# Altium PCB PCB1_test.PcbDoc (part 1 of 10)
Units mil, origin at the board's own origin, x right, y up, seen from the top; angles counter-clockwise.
Board outline 6690 x 6690 mil, 6 copper layers (Layer 1 - Top Layer, Layer 2 - GND, Layer 3 - PWR, Layer 4 - Signal, Layer 5 - GND, Layer 6 - Bottom Layer), stack 80.244 mil thick; 821 components, 458 nets, 3752 pads, 1525 vias.
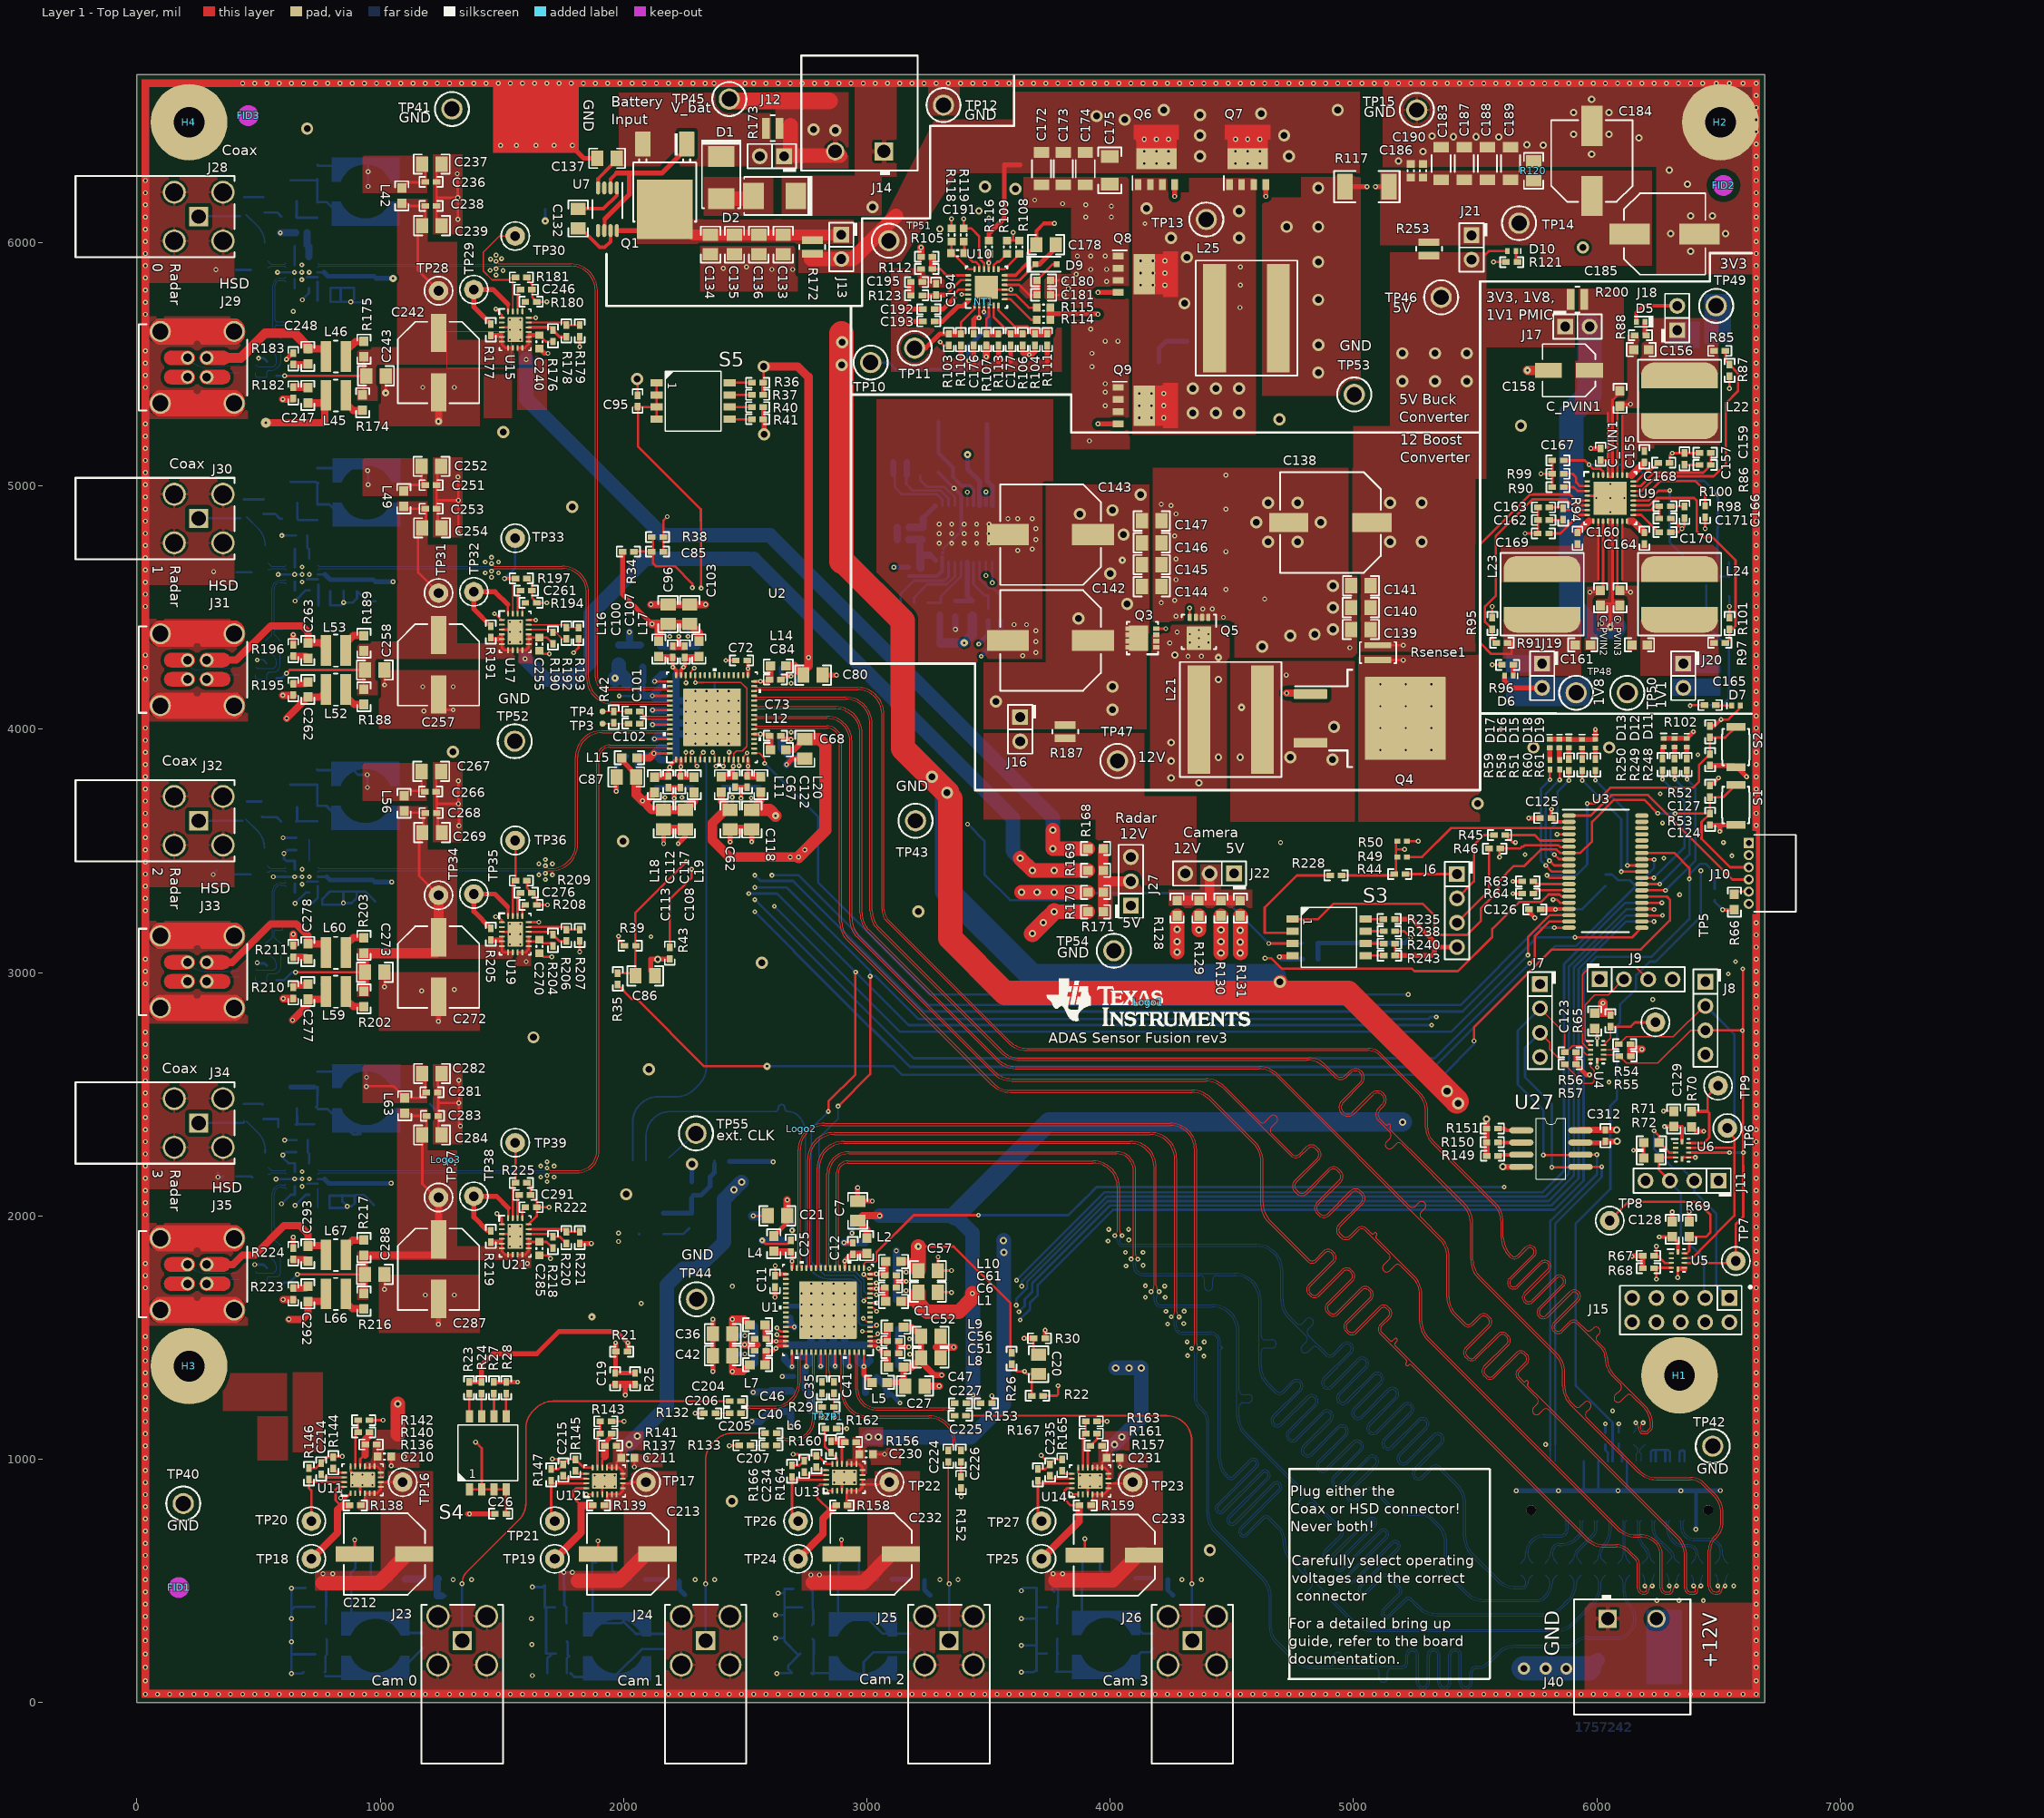
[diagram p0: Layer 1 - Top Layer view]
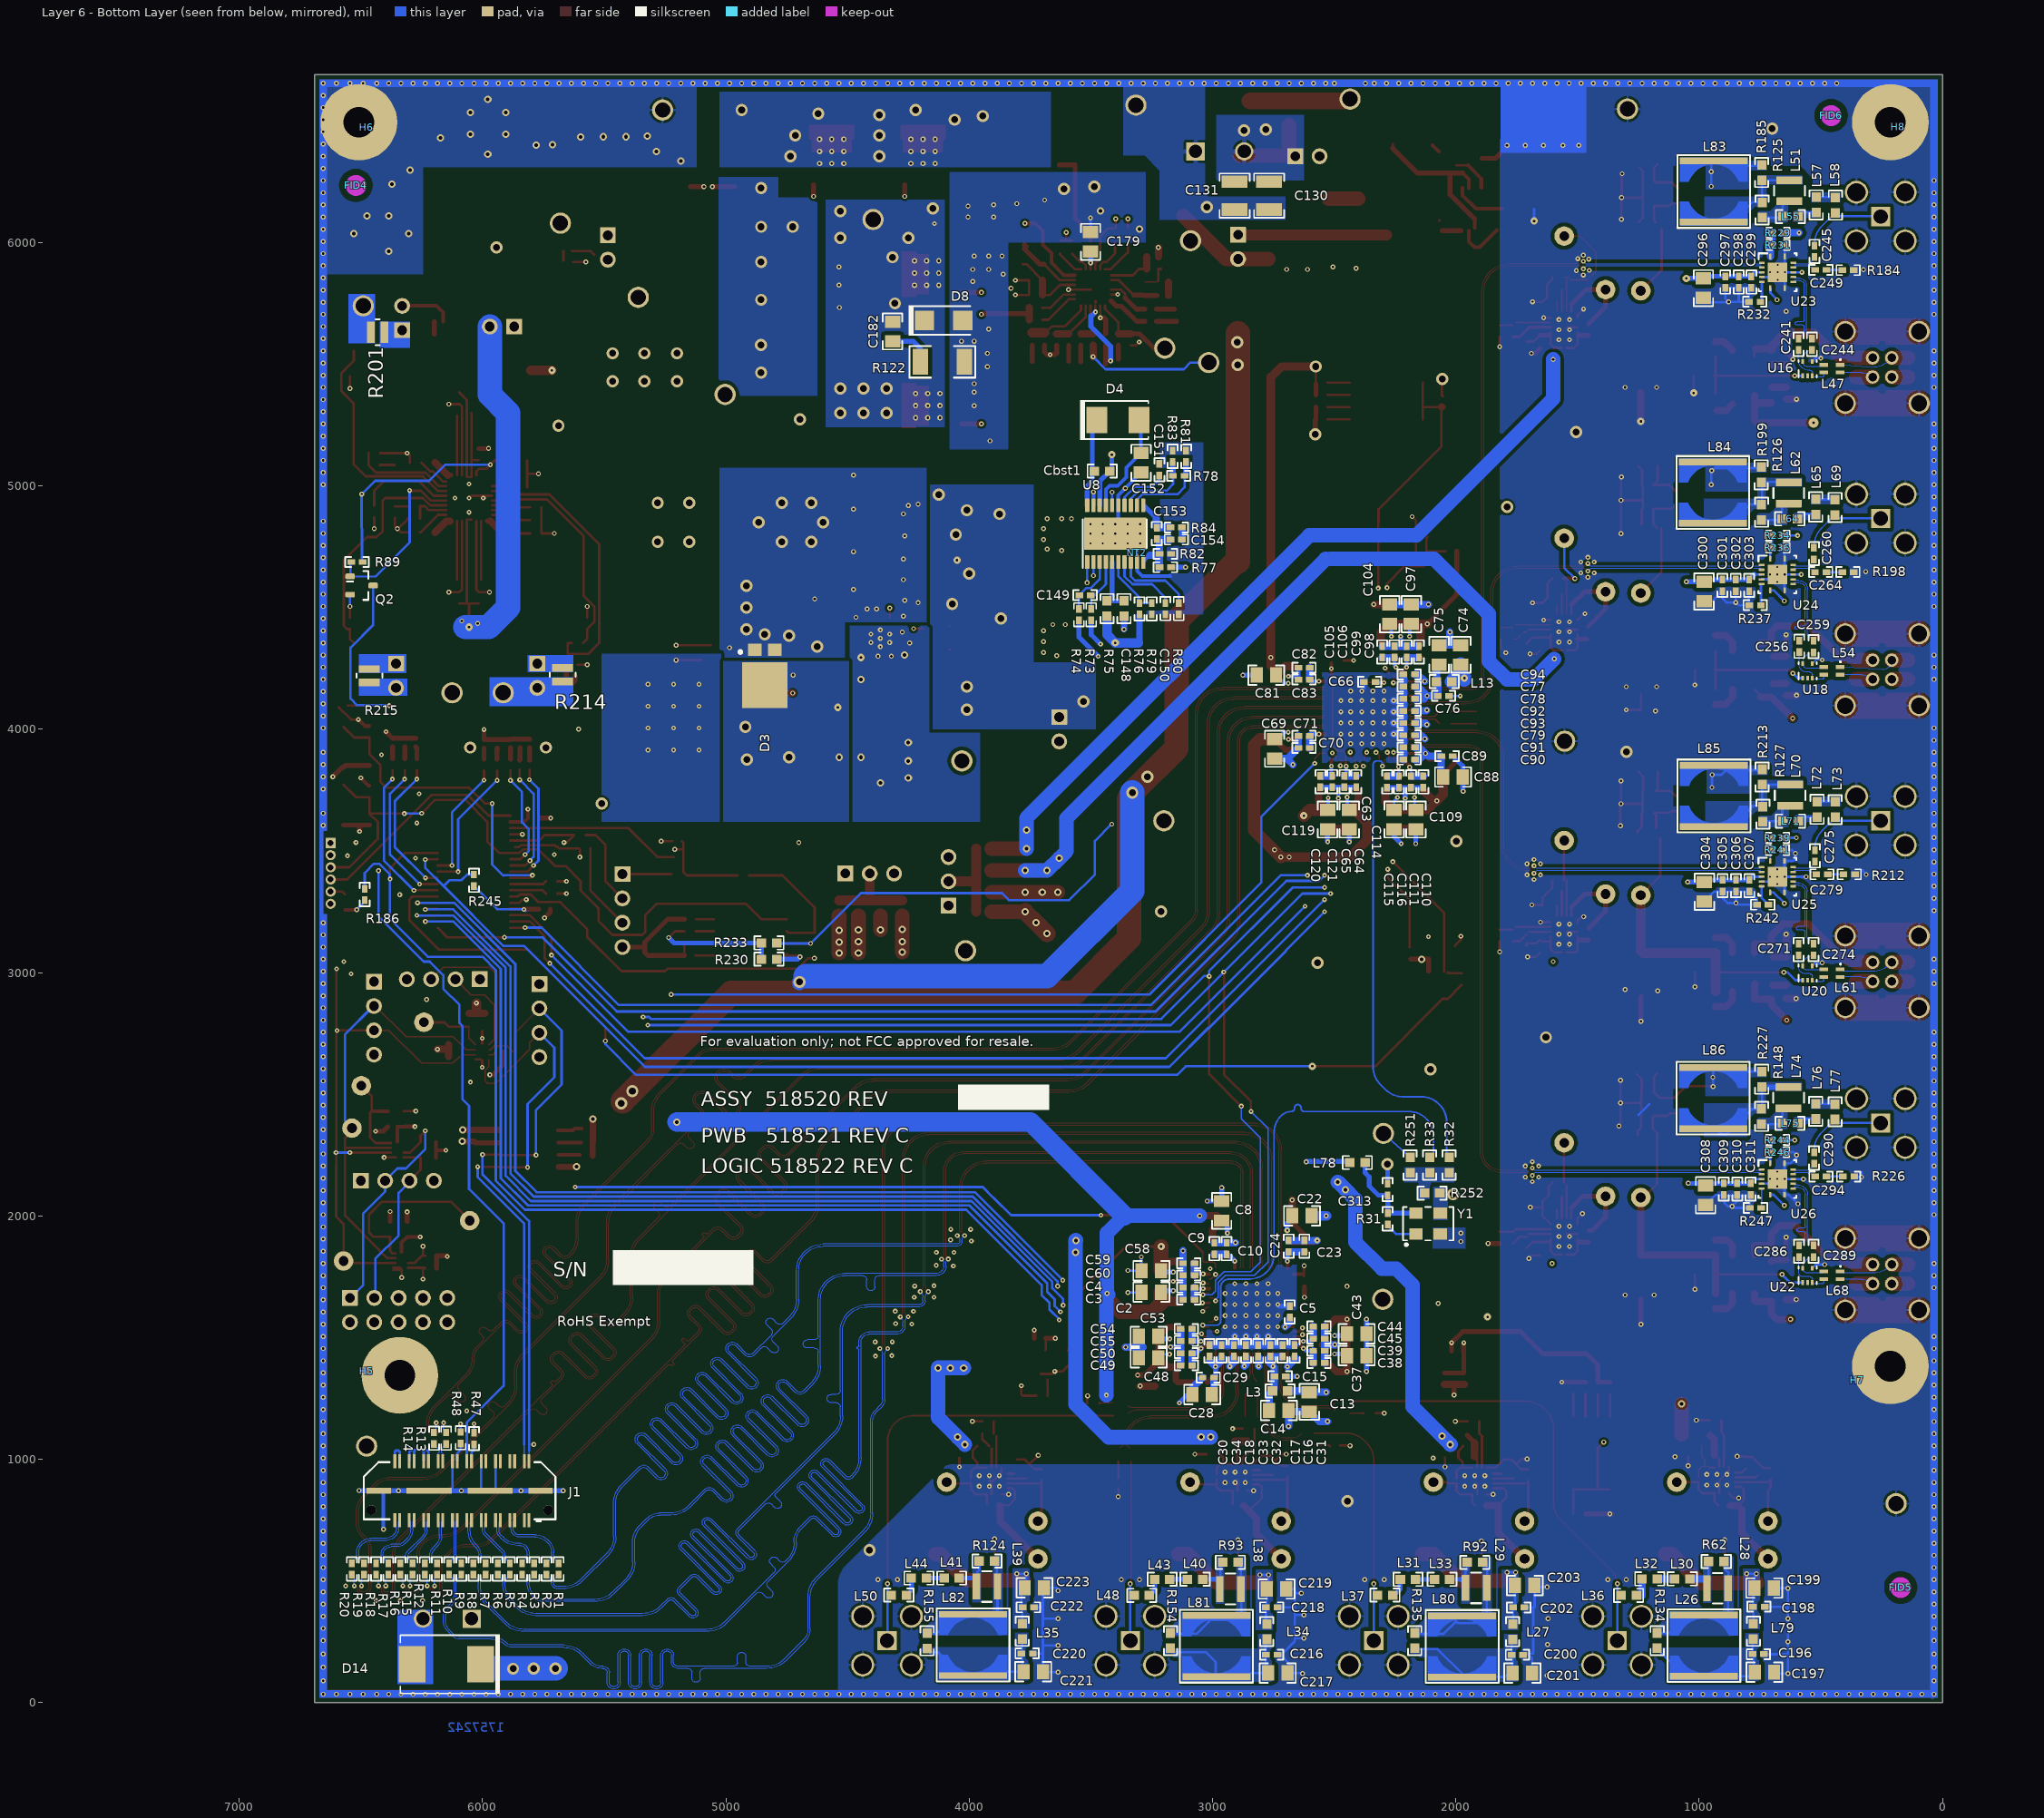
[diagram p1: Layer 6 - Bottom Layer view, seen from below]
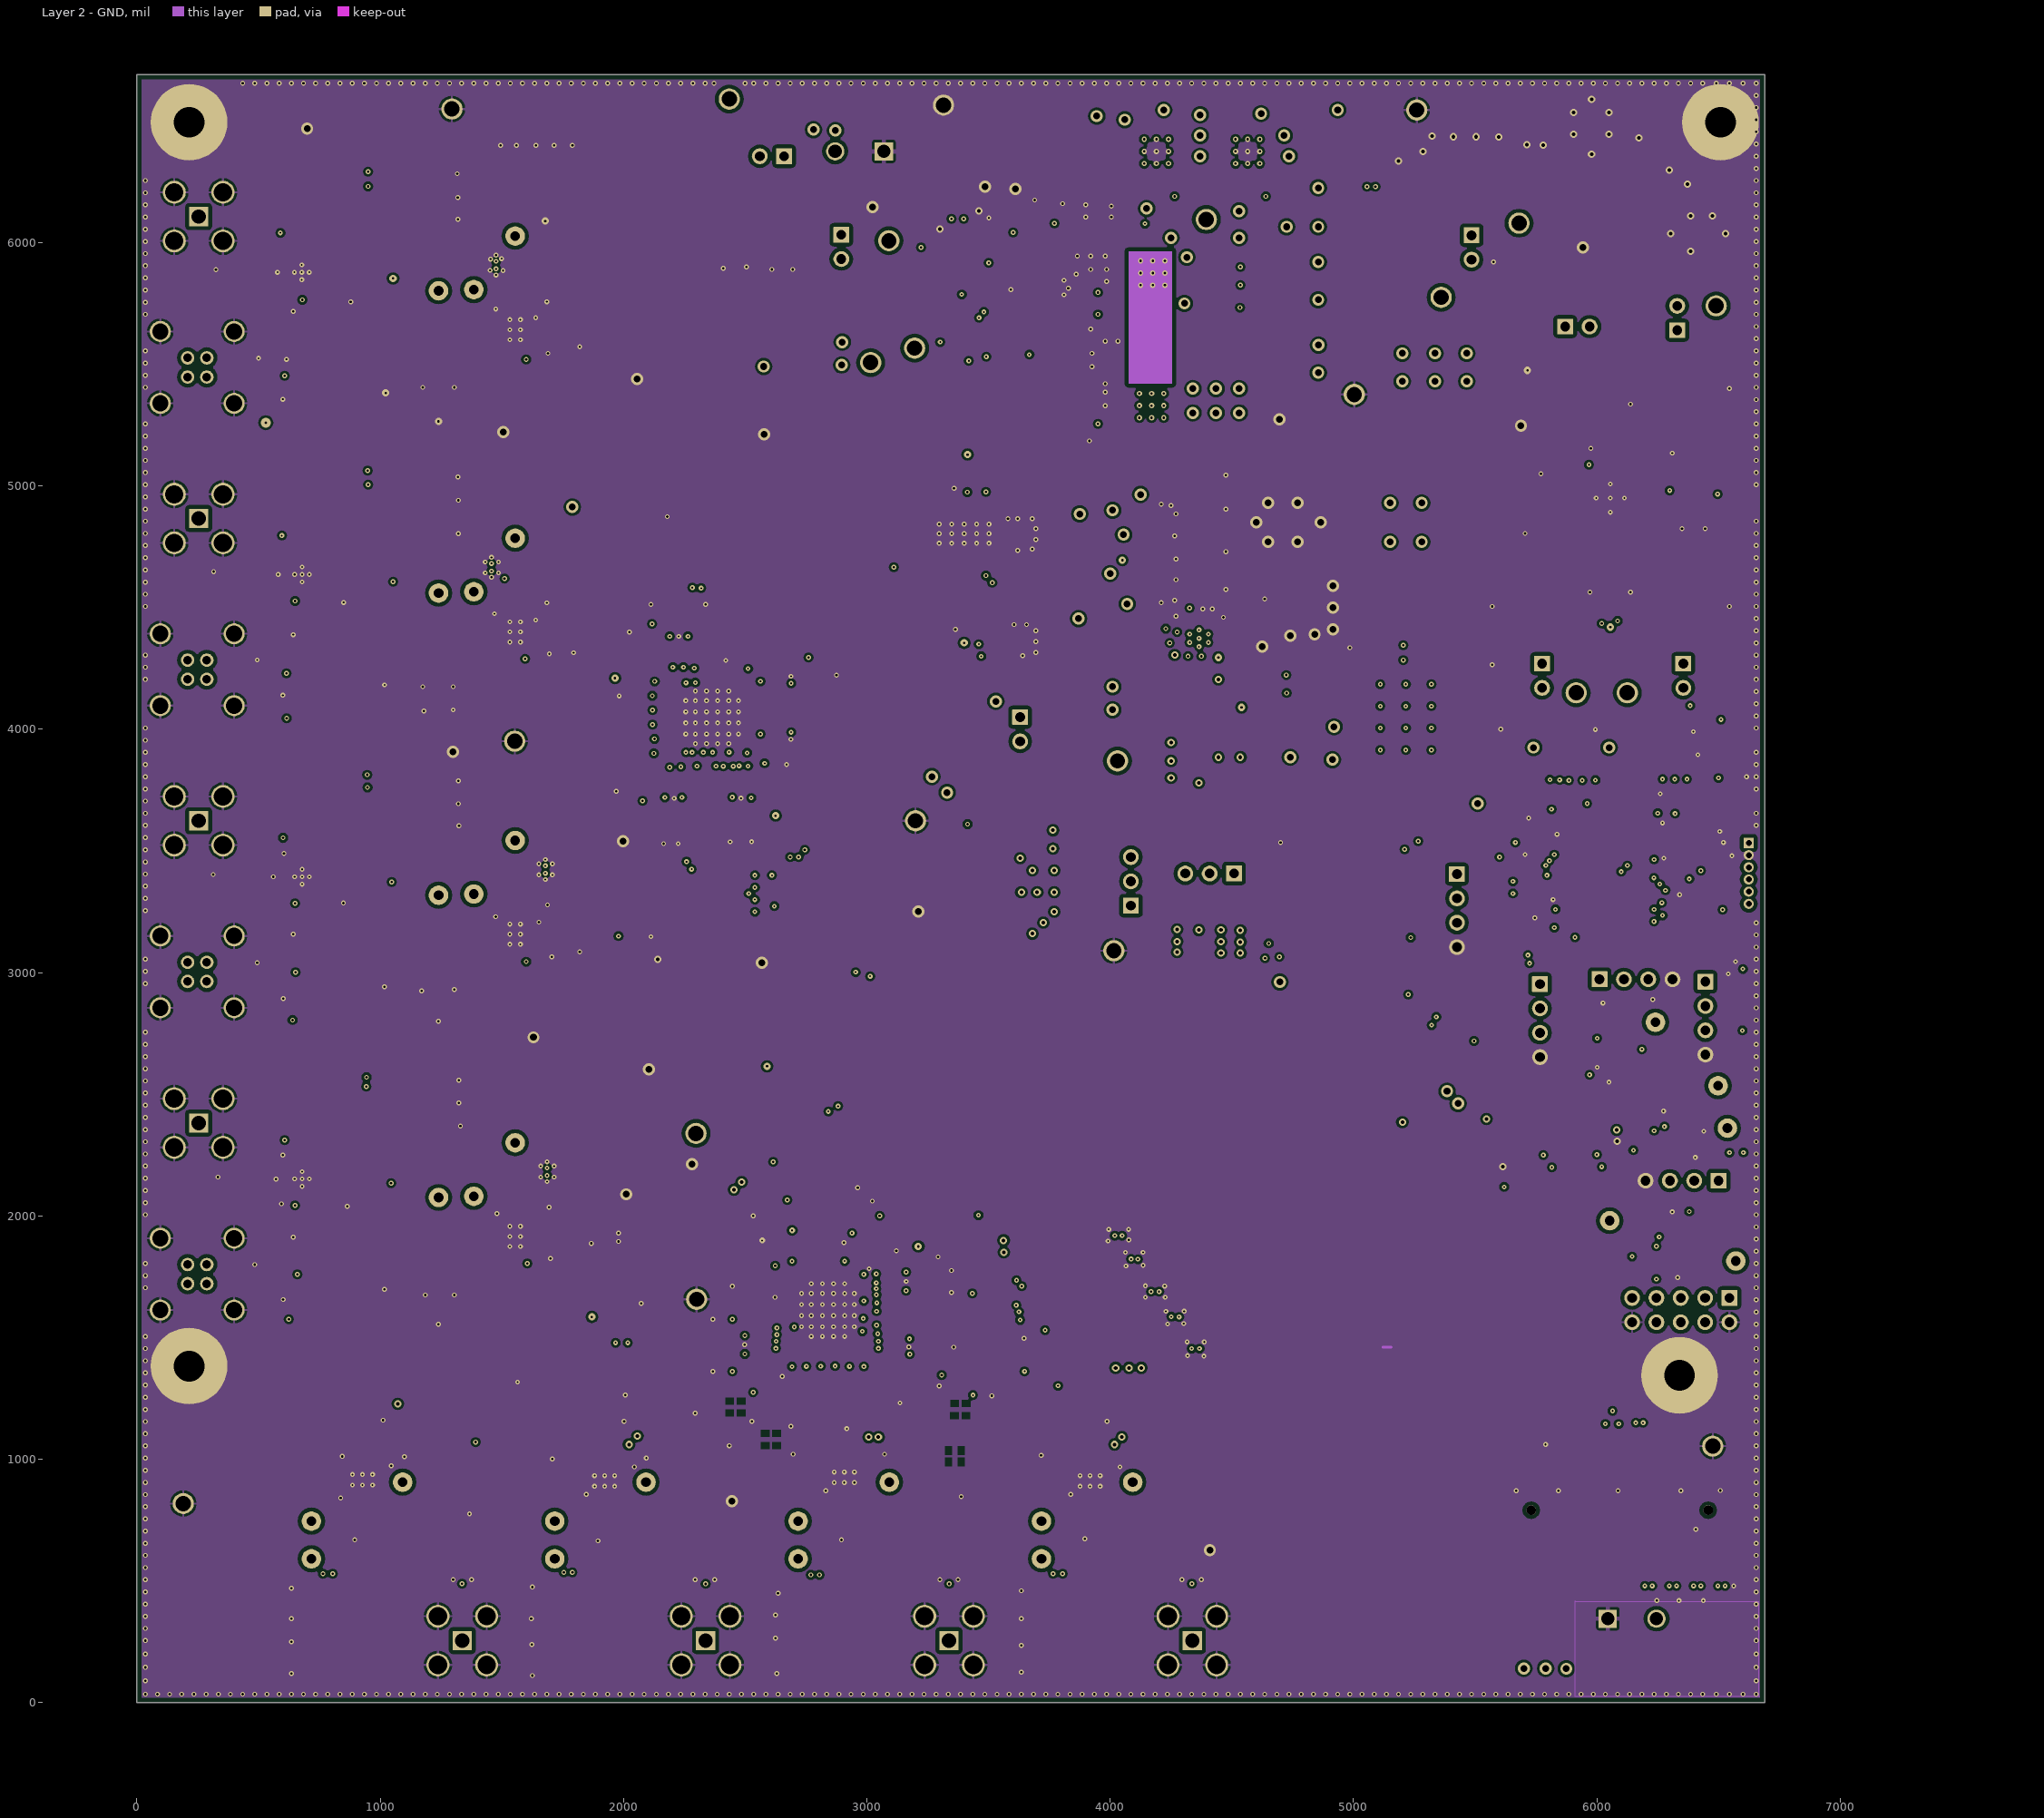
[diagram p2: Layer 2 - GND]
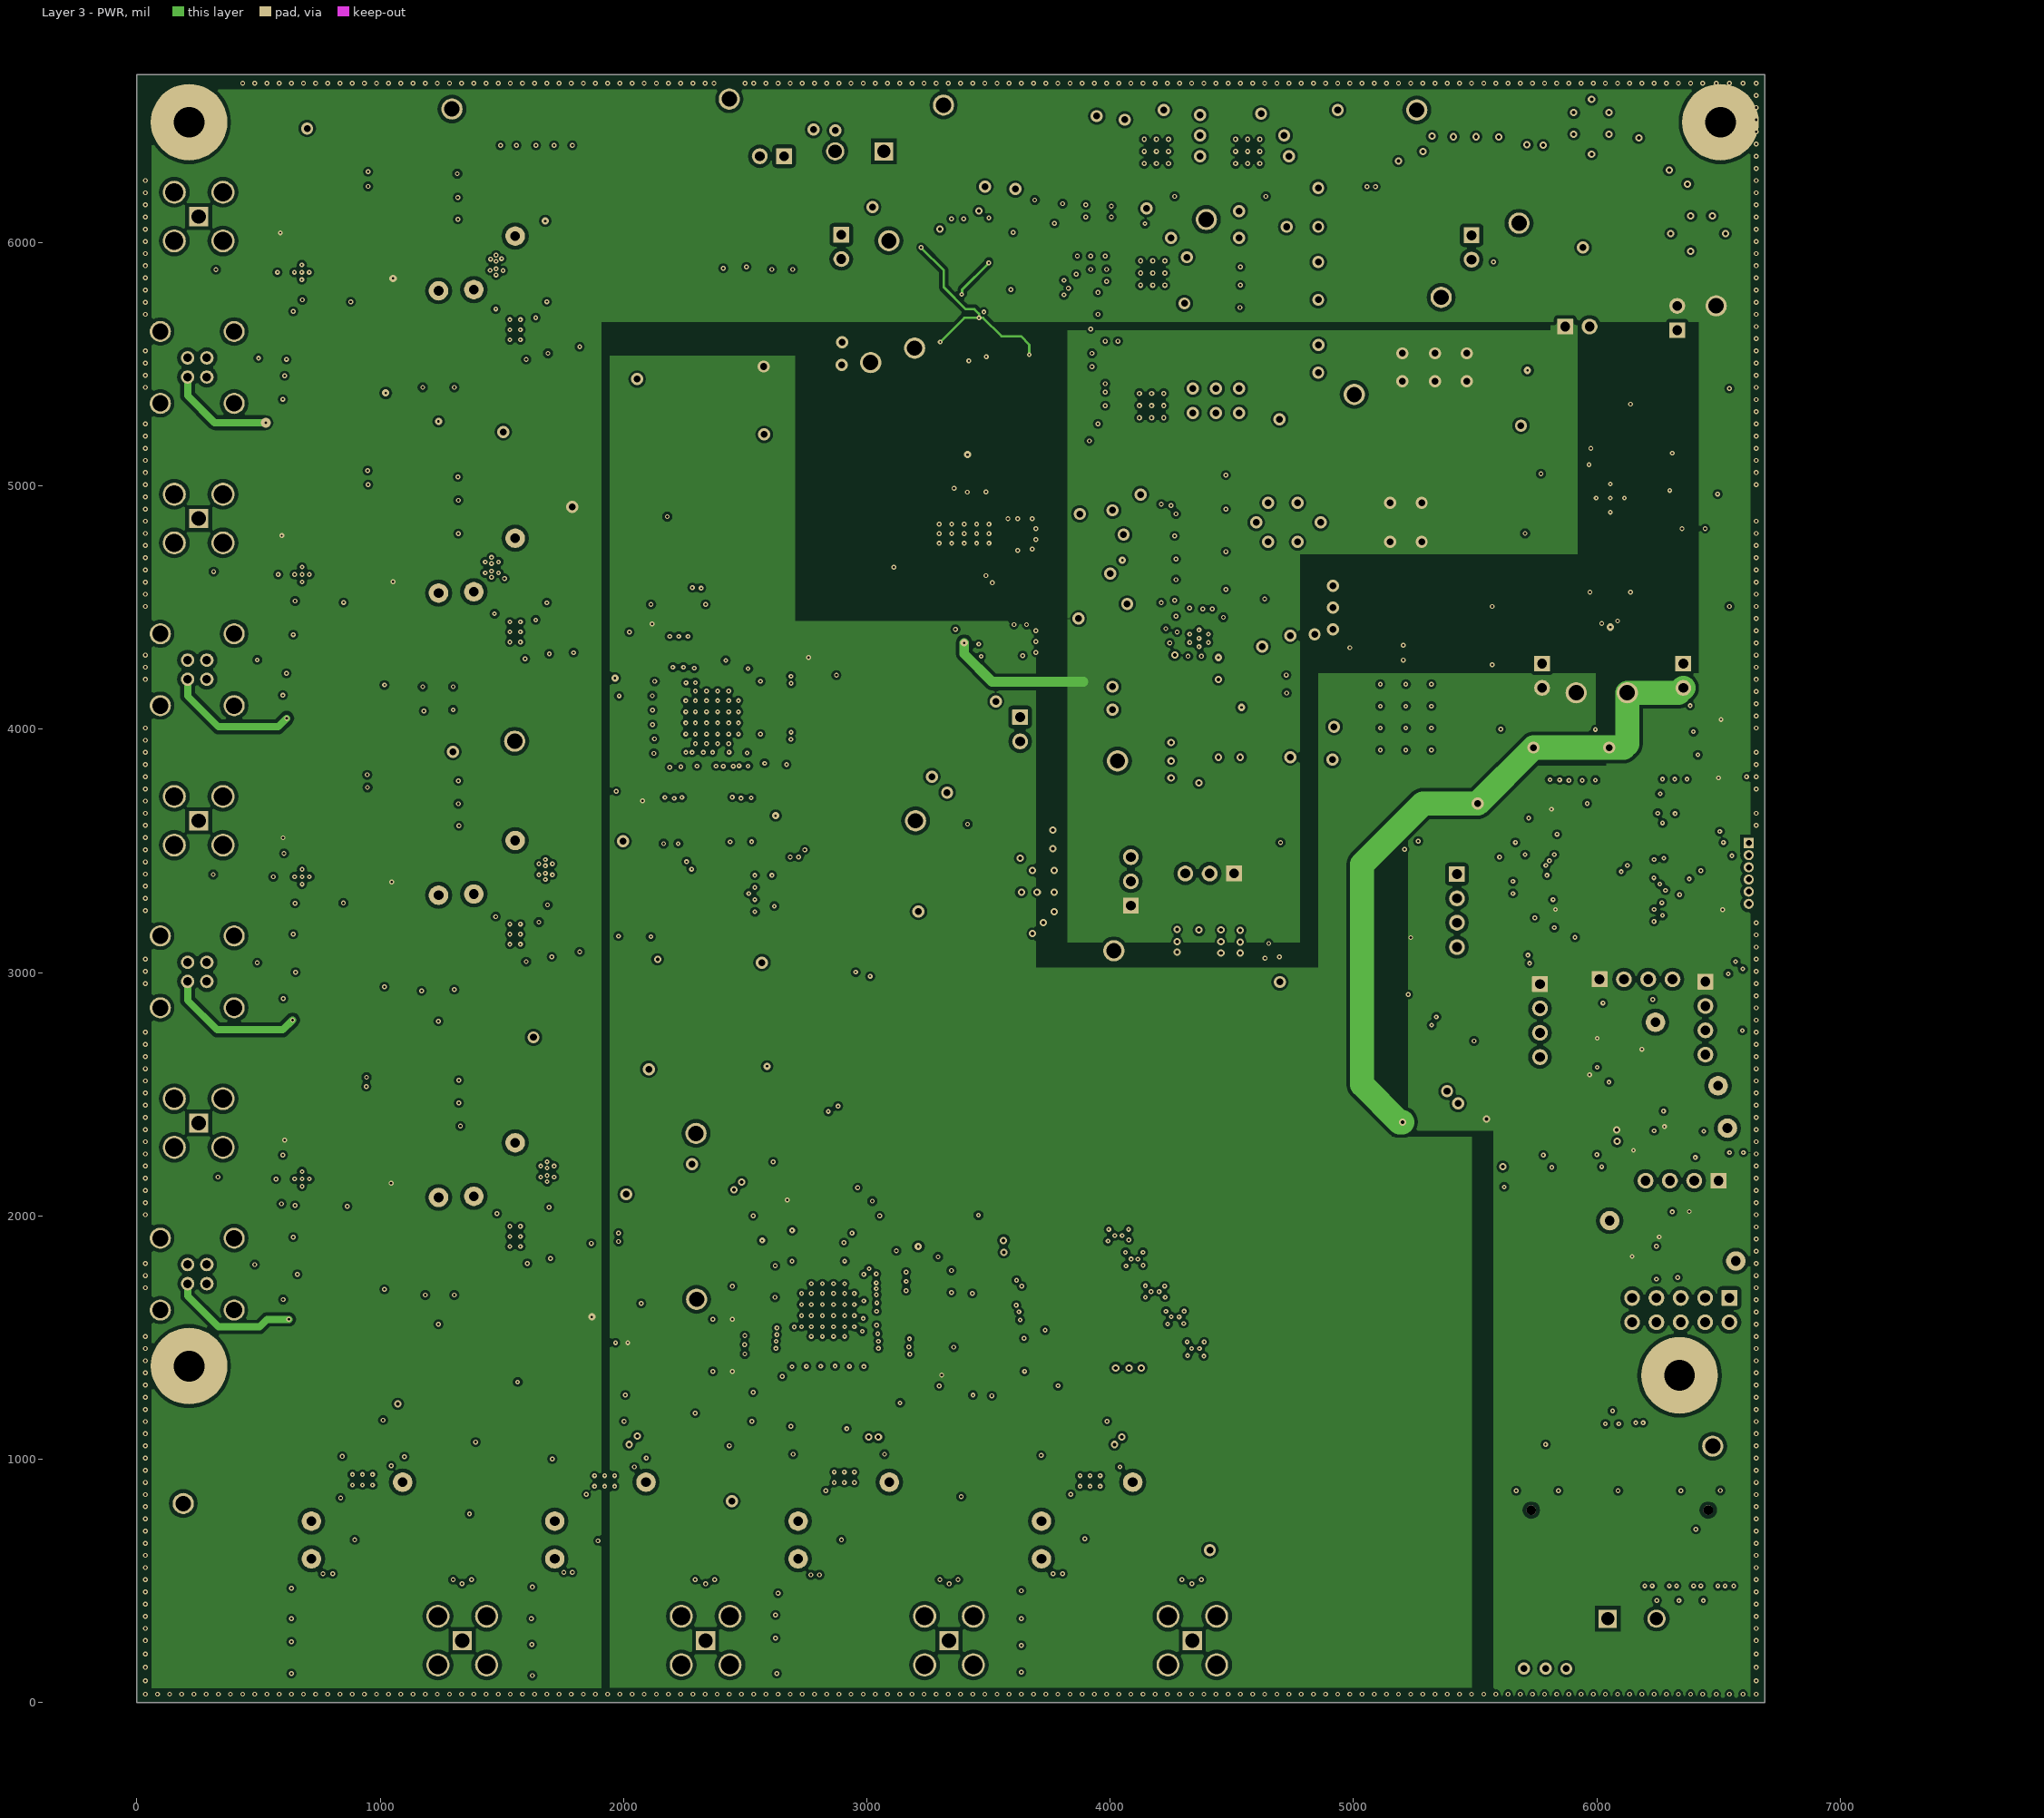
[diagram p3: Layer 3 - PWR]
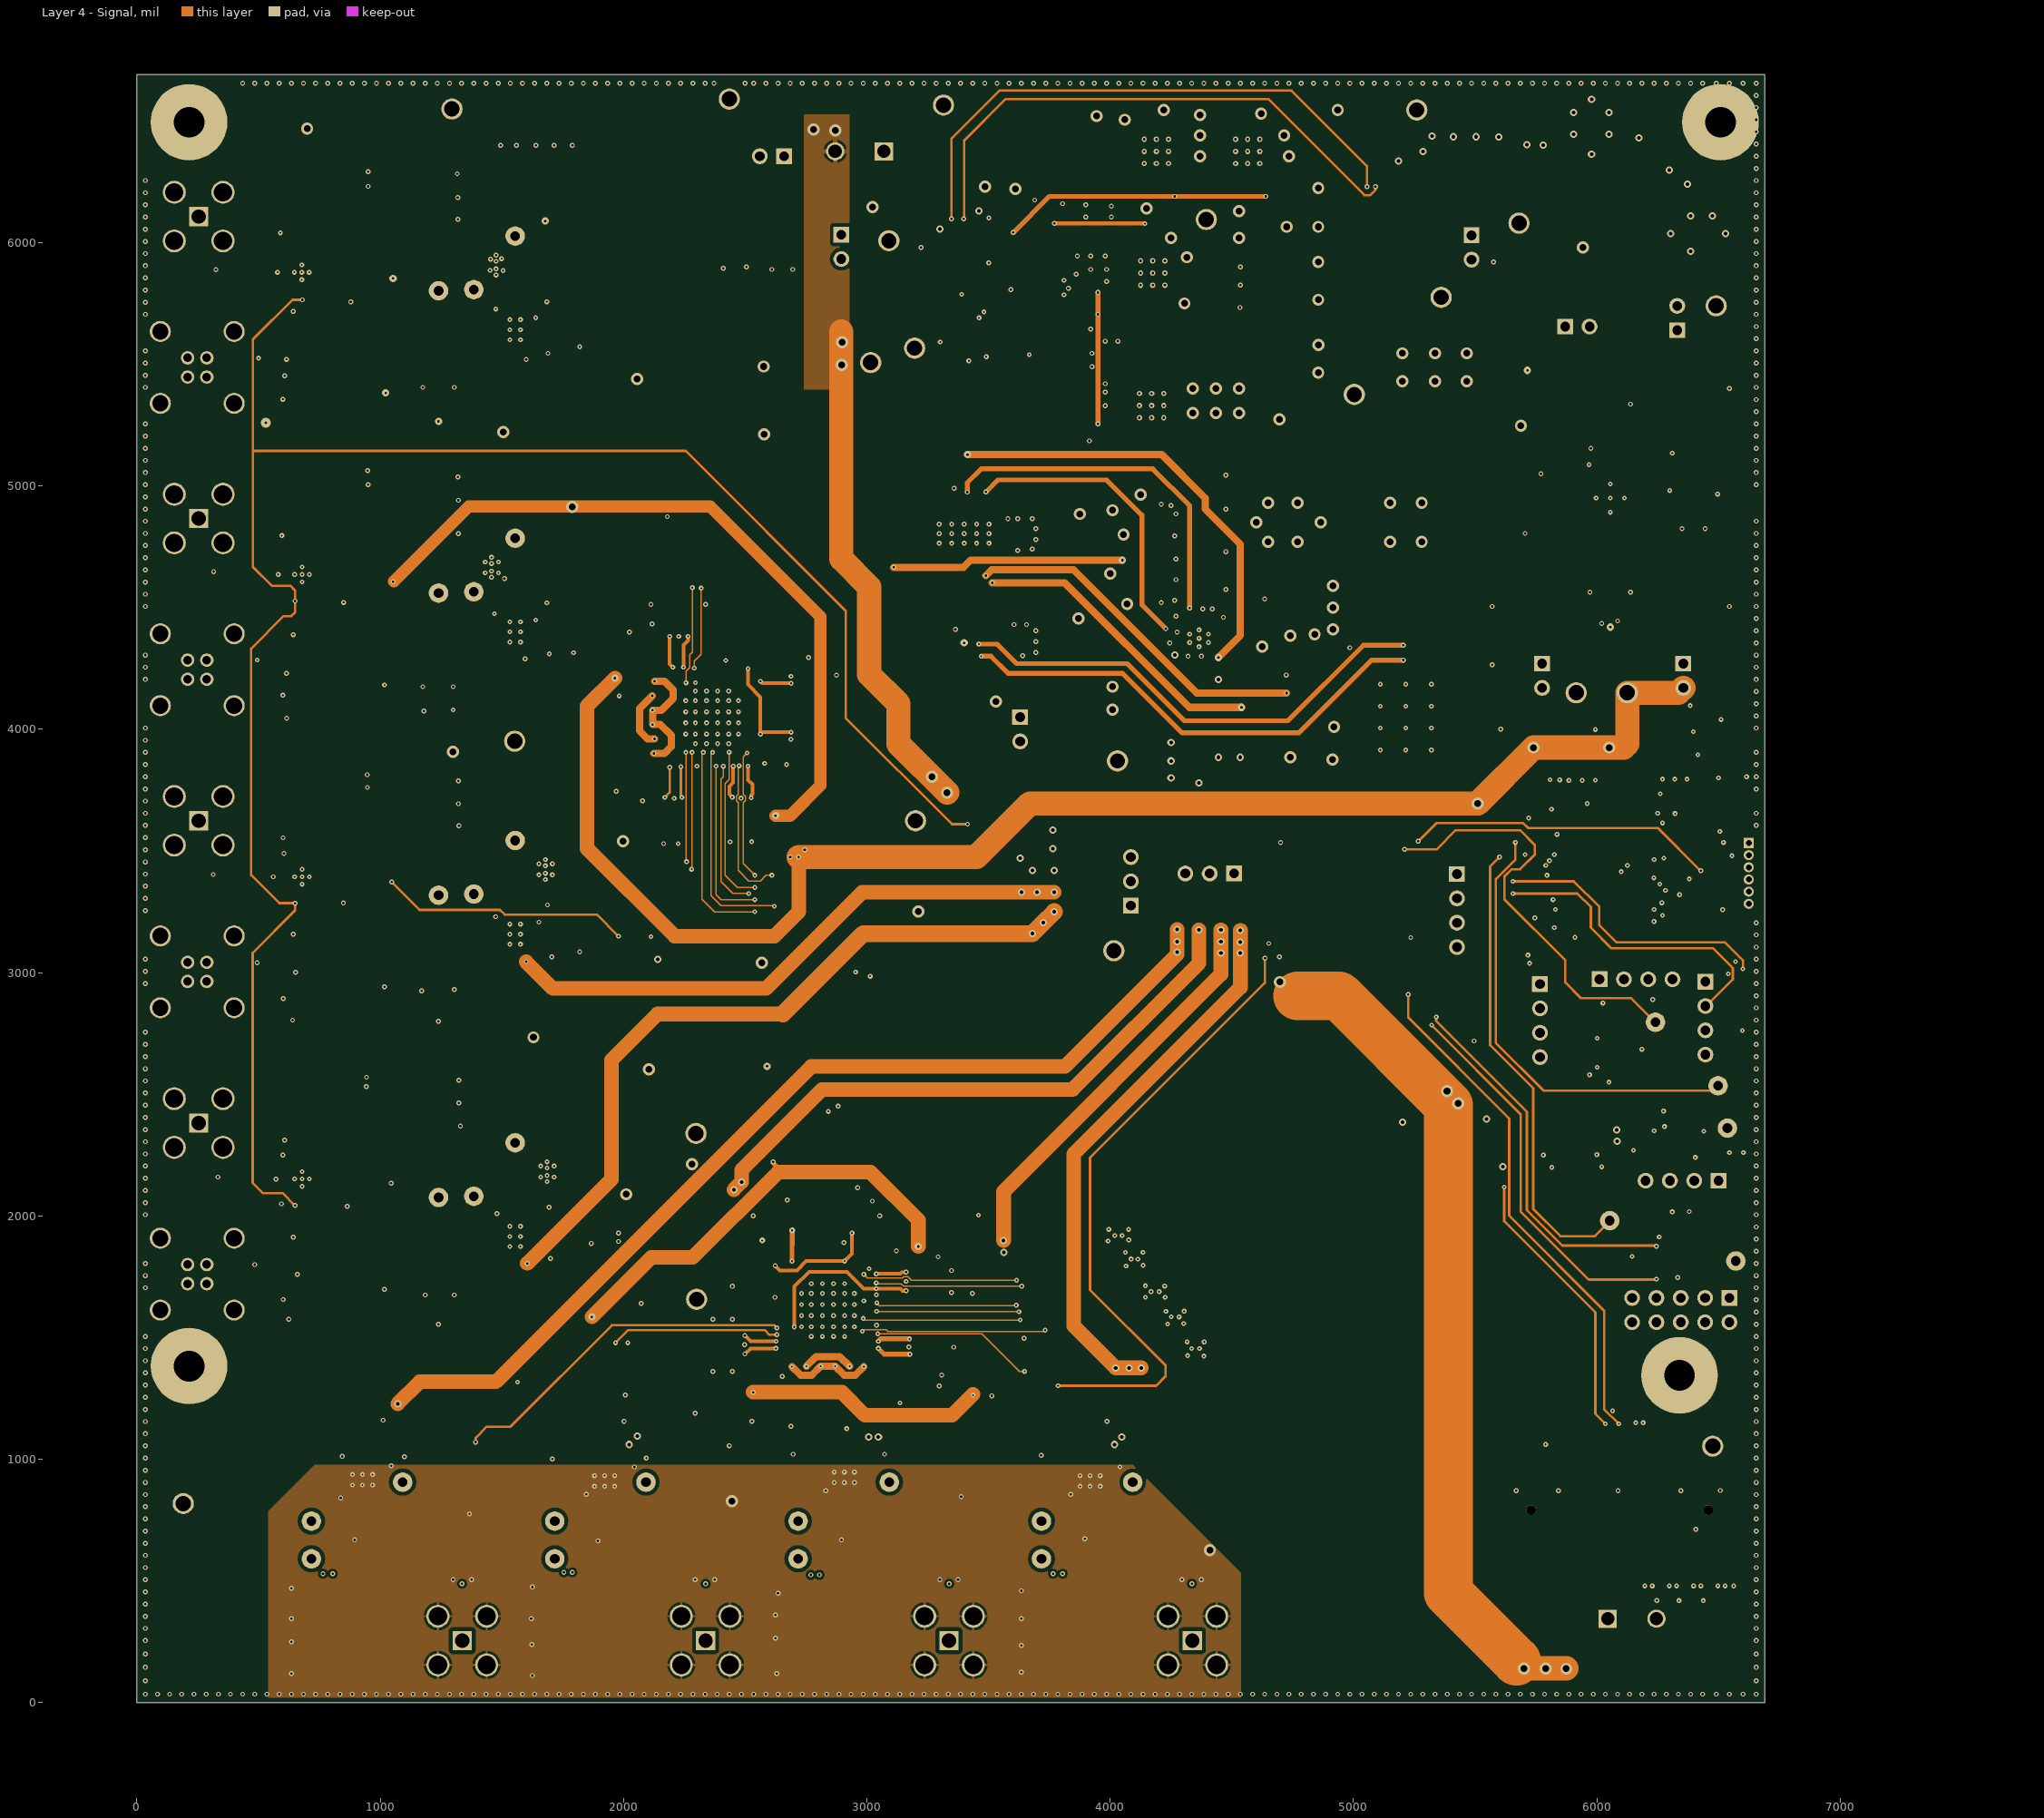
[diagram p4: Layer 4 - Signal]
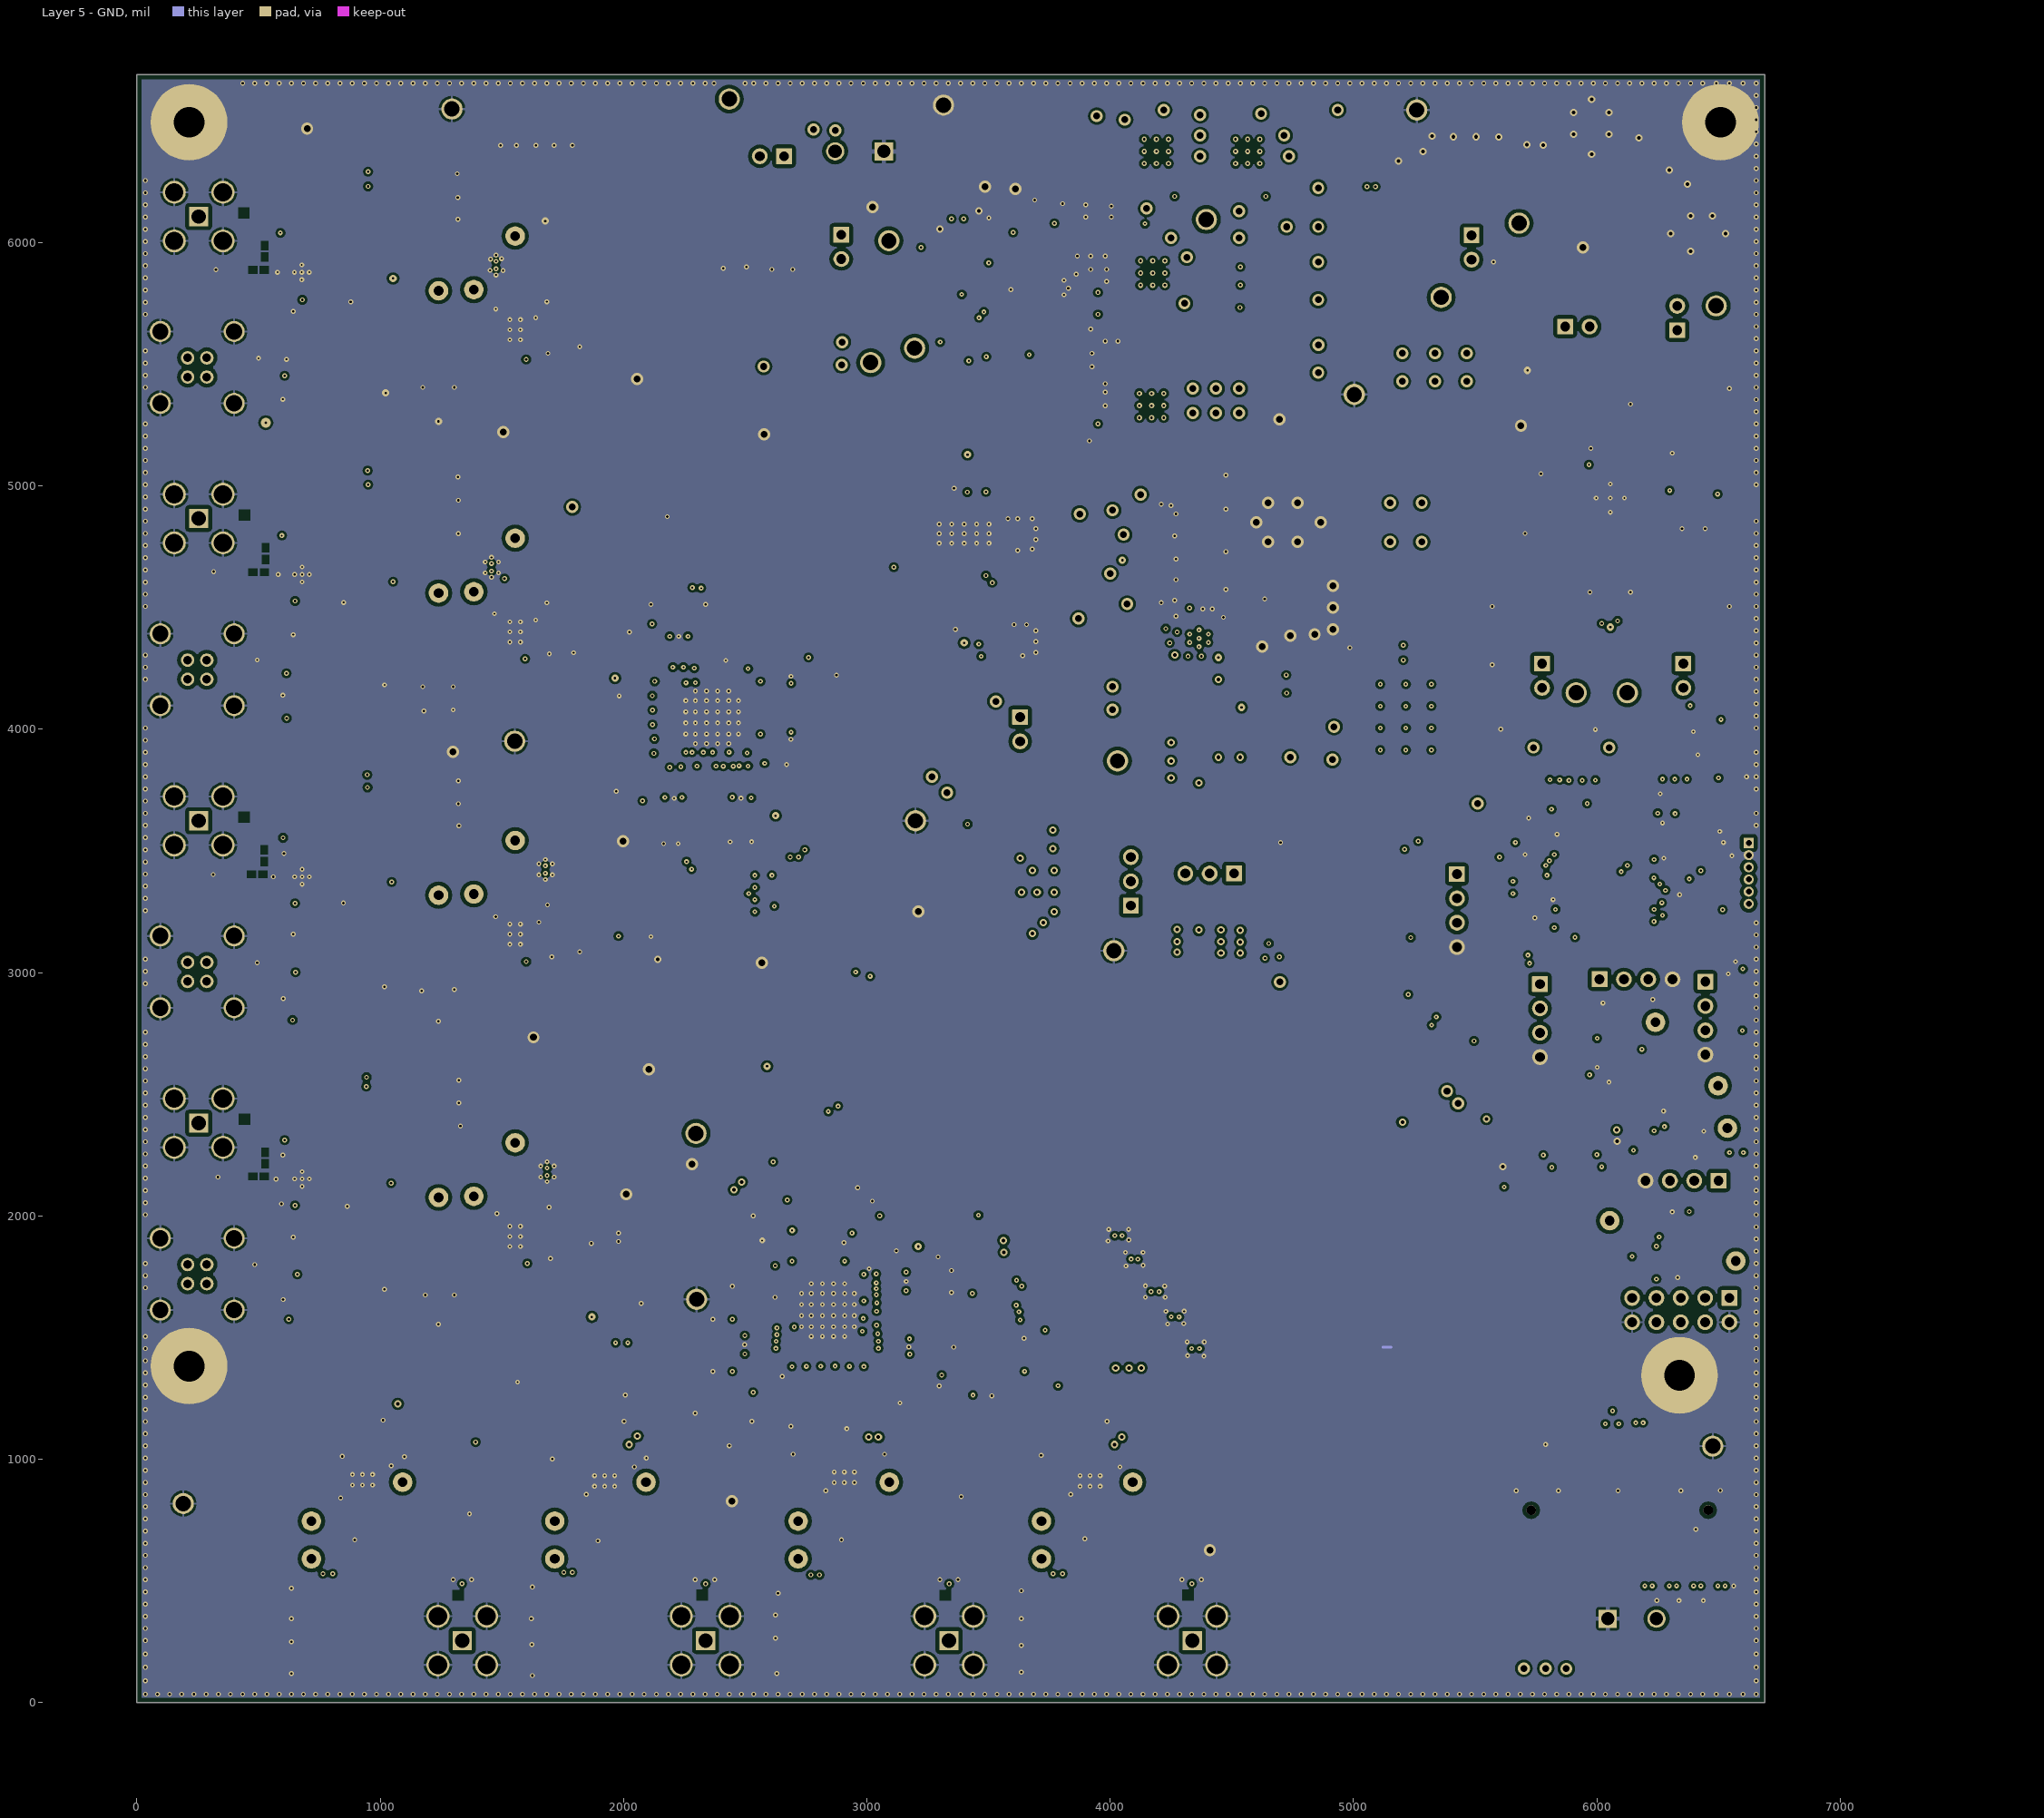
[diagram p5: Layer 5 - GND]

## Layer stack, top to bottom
Top Solder: solder mask 0.5, Solder Resist, Dk 3.5
Layer 1 - Top Layer: signal copper 1.7
Dielectric1: prepreg 4.055, 370HR, Dk 4.2
Layer 2 - GND: signal copper 1.181
Dielectric2: core 27.95, 370HR, Dk 4.2
Layer 3 - PWR: signal copper 1.181
Dielectric3: prepreg 8.11, 370HR, Dk 4.2
Layer 4 - Signal: signal copper 1.181
Dielectric4: core 27.95, 370HR, Dk 4.2
Layer 5 - GND: signal copper 1.181
Dielectric5: prepreg 4.055, 370HR, Dk 4.2
Layer 6 - Bottom Layer: signal copper 1.7
Bottom Solder: solder mask 0.5, Solder Resist, Dk 3.5

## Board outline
0,0 6690,0 6690,6690 0,6690

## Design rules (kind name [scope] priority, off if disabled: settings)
AcuteAngle [All] p1: minimum=4.49000000000000E+0001 checktracksonly=FALSE
AssemblyTestPointUsage [All] p1: valid=2
Clearance Clearance_Keepouts [((IsTrack Or IsArc) And Not InPoly) And IsFree and IsKeepOut vs ((IsTrack Or IsArc) And Not InPoly) And IsFree and IsKeepOut] p1: gap=0 ignorepadtopadclearanceinfootprint=FALSE
Clearance Clearance_BoardEdge_MountingHoles [OnCopper and InComponentClass('Mounting Holes') vs IsKeepOut] p2: gap=30 ignorepadtopadclearanceinfootprint=FALSE except(0: Arc-Hole Track-Hole SMDPad-Hole THPad-Hole Via-Hole Fill-Hole Poly-Hole Region-Hole Text-Hole)
Clearance Clearance_BoardEdge_Poly [OnCopper and InPoly vs IsKeepOut] p3: gap=25 ignorepadtopadclearanceinfootprint=FALSE except(0: Arc-Hole Track-Hole SMDPad-Hole THPad-Hole Via-Hole Fill-Hole Poly-Hole Region-Hole Text-Hole)
Clearance Clearance_BoardEdge [OnCopper and Not InComponentClass('Logo') and not InComponentClass('FiducialMark') and not InRegion(1000,500,4000,800) and Not IsKeepout vs IsKeepOut] p4: gap=75 ignorepadtopadclearanceinfootprint=FALSE except(0: Arc-Hole Track-Hole SMDPad-Hole THPad-Hole Via-Hole Fill-Hole Poly-Hole Region-Hole Text-Hole)
Clearance Clearance_Poly [InPolygon] p5: gap=15 ignorepadtopadclearanceinfootprint=FALSE except(0: Arc-Hole Track-Hole SMDPad-Hole THPad-Hole Via-Hole Fill-Hole Poly-Hole Region-Hole Text-Hole; 10: Via-Fill Via-Poly Via-Region)
Clearance [All] p6: gap=4 ignorepadtopadclearanceinfootprint=FALSE except(0: Arc-Hole Track-Hole SMDPad-Hole THPad-Hole Via-Hole Fill-Hole Poly-Hole Region-Hole Text-Hole)
ComponentClearance ComponentClearance_MountingHoles_FiducialMarks [InComponentClass('Mounting Holes') vs InComponentClass('FiducialMark')] p1: gap=50 collisioncheckmode=3 verticalgap=10 showdistances=FALSE
ComponentClearance ComponentClearance_Header [InComponent('J*')] p2: gap=0 collisioncheckmode=3 verticalgap=0 showdistances=FALSE
ComponentClearance ComponentClearance_Shunt [InComponentClass('Header') vs InComponentClass('Shunt')] p3: gap=0 collisioncheckmode=3 verticalgap=0 showdistances=FALSE
ComponentClearance ComponentClearance_Logo [InComponentClass('Logo')] p4: gap=50 collisioncheckmode=3 verticalgap=10 showdistances=FALSE
ComponentClearance ComponentClearance_ScrewToNut [(HasFootprint('NY PMS 440 0025 PH')) vs (HasFootprint('Keystone_1902C'))] p5: gap=5 collisioncheckmode=3 verticalgap=10 showdistances=FALSE
ComponentClearance ComponentClearance_MountingHoles [InComponentClass('Mounting Holes')] p6: gap=100 collisioncheckmode=3 verticalgap=0 showdistances=FALSE
ComponentClearance ComponentClearance_SmallPassives [HasFootprint('0201*') or HasFootprint('0402*') or HasFootprint('0508') or HasFootprint('0603*') or HasFootprint('0612') or HasFootprint('0805*') or HasFootprint('0815*') or HasFootprint('0830*') or HasFootprint('1206*') or HasFootprint('1210*') or HasFootprint('1808*') or HasFootprint('1812*') or HasFootprint('1825*') or HasFootprint('2010*') or HasFootprint('2220*') or HasFootprint('2225*') or HasFootprint('2512*') or HasFootprint('2728*') or HasFootprint('3518*') vs HasFootprint('0201*') or HasFootprint('0402*') or HasFootprint('0508') or HasFootprint('0603*') or HasFootprint('0612') or HasFootprint('0805*') or HasFootprint('0815*') or HasFootprint('0830*') or HasFootprint('1206*') or HasFootprint('1210*') or HasFootprint('1808*') or HasFootprint('1812*') or HasFootprint('1825*') or HasFootprint('2010*') or HasFootprint('2220*') or HasFootprint('2225*') or HasFootprint('2512*') or HasFootprint('2728*') or HasFootprint('3518*')] p7: gap=10 collisioncheckmode=3 verticalgap=10 showdistances=FALSE
ComponentClearance ComponentClearance_THtoSMT [IsThruComponent vs IsSMTComponent] p8: gap=20 collisioncheckmode=3 verticalgap=30 showdistances=FALSE
ComponentClearance ComponentClearance_THtoTH [IsThruComponent vs IsThruComponent] p9: gap=40 collisioncheckmode=3 verticalgap=30 showdistances=FALSE
ComponentClearance [All] p10: gap=10 collisioncheckmode=3 verticalgap=10 showdistances=FALSE
DiffPairsRouting "CSI2 Routing old" [InDifferentialPairClass('CSI2')] p1 off: maxlimit=10.63 minlimit=10 mostfreqgap=10.63 toplayer_minwidth=5.12 toplayer_maxwidth=5.91 toplayer_prefwidth=5.91 midlayer1_minwidth=5.12 midlayer1_maxwidth=5.91 midlayer1_prefwidth=5.91 midlayer2_minwidth=5.12 midlayer2_maxwidth=5.91 midlayer2_prefwidth=5.91 midlayer3_minwidth=5.12 midlayer3_maxwidth=5.91 midlayer3_prefwidth=5.91 midlayer4_minwidth=5.12 midlayer4_maxwidth=5.91 midlayer4_prefwidth=5.91 bottomlayer_minwidth=5.12 bottomlayer_maxwidth=5.91 bottomlayer_prefwidth=5.91 maxuncoupledlength=500
DiffPairsRouting "CSI2 Routing" [InDifferentialPairClass('CSI2')] p2 off: maxlimit=10.63 minlimit=5.12 mostfreqgap=5.12 toplayer_minwidth=3.94 toplayer_maxwidth=5.91 toplayer_prefwidth=3.94 midlayer1_minwidth=3.94 midlayer1_maxwidth=5.91 midlayer1_prefwidth=3.94 midlayer2_minwidth=3.94 midlayer2_maxwidth=5.91 midlayer2_prefwidth=3.94 midlayer3_minwidth=3.94 midlayer3_maxwidth=5.91 midlayer3_prefwidth=3.94 midlayer4_minwidth=3.94 midlayer4_maxwidth=5.91 midlayer4_prefwidth=3.94 bottomlayer_minwidth=3.94 bottomlayer_maxwidth=5.91 bottomlayer_prefwidth=3.94 maxuncoupledlength=500
DiffPairsRouting "CSI2 Connector old" [InDifferentialPairClass('CSI2 Connection')] p3 off: maxlimit=10.63 minlimit=10 mostfreqgap=10.63 toplayer_minwidth=5.12 toplayer_maxwidth=5.91 toplayer_prefwidth=5.91 midlayer1_minwidth=5.12 midlayer1_maxwidth=5.91 midlayer1_prefwidth=5.91 midlayer2_minwidth=5.12 midlayer2_maxwidth=5.91 midlayer2_prefwidth=5.91 midlayer3_minwidth=5.12 midlayer3_maxwidth=5.91 midlayer3_prefwidth=5.91 midlayer4_minwidth=5.12 midlayer4_maxwidth=5.91 midlayer4_prefwidth=5.91 bottomlayer_minwidth=5.12 bottomlayer_maxwidth=5.91 bottomlayer_prefwidth=5.91 maxuncoupledlength=500
DiffPairsRouting "CSI2 Connector" [InDifferentialPairClass('CSI2 Connection')] p4 off: maxlimit=10.63 minlimit=5.12 mostfreqgap=5.12 toplayer_minwidth=3.94 toplayer_maxwidth=5.91 toplayer_prefwidth=3.94 midlayer1_minwidth=3.94 midlayer1_maxwidth=5.91 midlayer1_prefwidth=3.94 midlayer2_minwidth=3.94 midlayer2_maxwidth=5.91 midlayer2_prefwidth=3.94 midlayer3_minwidth=3.94 midlayer3_maxwidth=5.91 midlayer3_prefwidth=3.94 midlayer4_minwidth=3.94 midlayer4_maxwidth=5.91 midlayer4_prefwidth=3.94 bottomlayer_minwidth=3.94 bottomlayer_maxwidth=5.91 bottomlayer_prefwidth=3.94 maxuncoupledlength=500
DiffPairsRouting "FPD Link CAM" [InDifferentialPairClass('CAM_FPD_LINK')] p5 off: maxlimit=10.63 minlimit=10 mostfreqgap=10.63 toplayer_minwidth=5.12 toplayer_maxwidth=5.91 toplayer_prefwidth=5.91 midlayer1_minwidth=5.12 midlayer1_maxwidth=5.91 midlayer1_prefwidth=5.91 midlayer2_minwidth=5.12 midlayer2_maxwidth=5.91 midlayer2_prefwidth=5.91 midlayer3_minwidth=5.12 midlayer3_maxwidth=5.91 midlayer3_prefwidth=5.91 midlayer4_minwidth=5.12 midlayer4_maxwidth=5.91 midlayer4_prefwidth=5.91 bottomlayer_minwidth=5.12 bottomlayer_maxwidth=5.91 bottomlayer_prefwidth=5.91 maxuncoupledlength=500
DiffPairsRouting "FPD Link Radar" [InDifferentialPairClass('RADAR_FPD_LINK')] p6 off: maxlimit=10.63 minlimit=10 mostfreqgap=10.63 toplayer_minwidth=5.12 toplayer_maxwidth=5.91 toplayer_prefwidth=5.91 midlayer1_minwidth=5.12 midlayer1_maxwidth=5.91 midlayer1_prefwidth=5.91 midlayer2_minwidth=5.12 midlayer2_maxwidth=5.91 midlayer2_prefwidth=5.91 midlayer3_minwidth=5.12 midlayer3_maxwidth=5.91 midlayer3_prefwidth=5.91 midlayer4_minwidth=5.12 midlayer4_maxwidth=5.91 midlayer4_prefwidth=5.91 bottomlayer_minwidth=5.12 bottomlayer_maxwidth=5.91 bottomlayer_prefwidth=5.91 maxuncoupledlength=500
DiffPairsRouting "FPD Link Radar_Connector" [InDifferentialPairClass('Radar Connector')] p7 off: maxlimit=10.63 minlimit=10 mostfreqgap=10.63 toplayer_minwidth=5.12 toplayer_maxwidth=5.91 toplayer_prefwidth=5.91 midlayer1_minwidth=5.12 midlayer1_maxwidth=5.91 midlayer1_prefwidth=5.91 midlayer2_minwidth=5.12 midlayer2_maxwidth=5.91 midlayer2_prefwidth=5.91 midlayer3_minwidth=5.12 midlayer3_maxwidth=5.91 midlayer3_prefwidth=5.91 midlayer4_minwidth=5.12 midlayer4_maxwidth=5.91 midlayer4_prefwidth=5.91 bottomlayer_minwidth=5.12 bottomlayer_maxwidth=5.91 bottomlayer_prefwidth=5.91 maxuncoupledlength=500
DiffPairsRouting [All] p8: maxlimit=10 minlimit=5.12 mostfreqgap=5.12 toplayer_minwidth=3.94 toplayer_maxwidth=7 toplayer_prefwidth=3.94 midlayer1_minwidth=3.94 midlayer1_maxwidth=7 midlayer1_prefwidth=3.94 midlayer2_minwidth=3.94 midlayer2_maxwidth=7 midlayer2_prefwidth=3.94 midlayer3_minwidth=3.94 midlayer3_maxwidth=7 midlayer3_prefwidth=3.94 midlayer4_minwidth=3.94 midlayer4_maxwidth=7 midlayer4_prefwidth=3.94 bottomlayer_minwidth=3.94 bottomlayer_maxwidth=7 bottomlayer_prefwidth=3.94 maxuncoupledlength=1000
FabricationTestPointUsage TestPointUsage [All] p1: valid=2 allowmultiple=FALSE
FabricationTestpoint Testpoint [All] p1: side=3 testpointundercomponent=TRUE minsize=40 maxsize=100 preferedsize=60 minholesize=0 maxholesize=40 preferedholesize=32 testpointgrid=1 allowsidetop=TRUE allowsidebottom=TRUE usegrid=TRUE gridtolerance=0.01
FanoutControl Fanout_LCC [IsLCC] p1: bgadir=Out bgaviamode=Centered fanoutstyle=Auto fanoutdirection=Alternating viagrid=1 // Fanout_LCC (Default Rule)
FanoutControl Fanout_BGA [IsBGA] p2: bgadir=Out bgaviamode=Centered fanoutstyle=Auto fanoutdirection=Alternating viagrid=1 // Fanout_BGA (Default Rule)
FanoutControl Fanout_Default [All] p4: bgadir=Out bgaviamode=Centered fanoutstyle=Auto fanoutdirection=Alternating viagrid=1 // Fanout_Default (Default Rule)
FanoutControl Fanout_Small [(CompPinCount < 5)] p5: bgadir=Out bgaviamode=Centered fanoutstyle=Auto fanoutdirection=OutThenIn viagrid=1 // Fanout_Small (Default Rule)
HoleSize [All] p1: absolutevalues=TRUE maxlimit=251 minlimit=5 maxpercent=80.000 minpercent=20.000
HoleSize HoleSize_1 [All] p2: absolutevalues=TRUE maxlimit=251 minlimit=7.87 maxpercent=80.000 minpercent=20.000
MatchedLengths Mux_In [InNetClass('Mux_In')] p1: tolerance=2 checknetsindiffpair=FALSE checkdiffpairvsdiffpair=TRUE checkxsignals=TRUE checkothers=TRUE
MatchedLengths "HSD connector" [InNetClass('HSD Connector')] p2: tolerance=1 checknetsindiffpair=FALSE checkdiffpairvsdiffpair=TRUE checkxsignals=TRUE checkothers=TRUE
MatchedLengths MatchLengths_xSignals_J1_U1,U2 [InxSignalClass('xSignals_J1_U1,U2_MatchLengthsClass')] p3: tolerance=5 checknetsindiffpair=FALSE checkdiffpairvsdiffpair=TRUE checkxsignals=TRUE checkothers=TRUE
MatchedLengths FPD_Link_Cam [InNetClass('FPD_complete')] p4 off: tolerance=5 checknetsindiffpair=FALSE checkdiffpairvsdiffpair=TRUE checkxsignals=TRUE checkothers=TRUE
MatchedLengths Connector [InNetClass('CSI2 Connector')] p5: tolerance=1 checknetsindiffpair=FALSE checkdiffpairvsdiffpair=TRUE checkxsignals=TRUE checkothers=TRUE
MatchedLengths CSI2 [InNetClass('CSI2')] p6: tolerance=4 checknetsindiffpair=FALSE checkdiffpairvsdiffpair=TRUE checkxsignals=TRUE checkothers=TRUE
MinimumAnnularRing MinimumAnnularRing_ThermalPadVias [IsVia and InAnyComponent] p1: minimumring=3.94
MinimumAnnularRing [All] p2: minimumring=2.5
MinimumSolderMaskSliver MinimumSolderMaskSliver_Logo [InComponentClass('Logo') vs InComponentClass('Logo')] p1: minsoldermaskwidth=0.7
MinimumSolderMaskSliver [All] p2: minsoldermaskwidth=3.9
PlaneConnect [All] p1: planeconnectstyle=Relief reliefexpansion=10 reliefentries=4 reliefconductorwidth=10 reliefairgap=10
PolygonConnect PolygonConnect_3 [HasFootprint('PHOENIX_1757242')] p1: connectstyle=Relief reliefconductorwidth=20 reliefentries=4 polygonreliefangle="90 Angle" airgapwidth=10
PolygonConnect PolygonConnect_1 [( InComponent('TP12')  OR InComponent('TP45')  OR InComponent('TP46')  OR InComponent('TP47')  OR InComponent('TP48')  OR InComponent('TP49')  OR InComponent('TP50')  OR InComponent('TP51')  OR IsVia         OR InNet('12V') OR InNet('5V')  OR InNet('1V8') OR InNet('3V3') OR InNet('1V1') OR InNet('NetJ22_2') OR InNet('NetJ27_2') )] p2: connectstyle=Direct reliefconductorwidth=10 reliefentries=4 polygonreliefangle="90 Angle" airgapwidth=10
PolygonConnect PolygonConnect_2 [( HasFootprint('Rosenberger_59S20X-400L5') OR HasFootprint('Rosenberger_D4S20L-40MA5') OR HasFootprint('TSW-105-07-G-D') OR HasFootprint('Keystone5011'))] p3: connectstyle=Relief reliefconductorwidth=10 reliefentries=4 polygonreliefangle="90 Angle" airgapwidth=10
PolygonConnect [All] p4: connectstyle=Direct reliefconductorwidth=10 reliefentries=4 polygonreliefangle="90 Angle" airgapwidth=10
RoutingVias ThermalPadVias [IsVia and InAnyComponent] p1: holewidth=7.87 width=19.68 viastyle="Through Hole" minholewidth=7.87 minwidth=15.75 maxholewidth=12.99 maxwidth=23.62
RoutingVias [All] p2: holewidth=16 width=34 viastyle="Through Hole" minholewidth=5 minwidth=10 maxholewidth=40 maxwidth=65
SilkToSilkClearance SilkToSilkClearance_Pb-FreeLogo [(HasFootprint('Pb-Free_Overlay_Medium') OR HasFootprint('Pb-Free_Overlay_Small')) vs (HasFootprint('Pb-Free_Overlay_Medium') OR HasFootprint('Pb-Free_Overlay_Small'))] p1: silktosilkclearance=0
SilkToSilkClearance [All] p2: silktosilkclearance=1
SilkToSolderMaskClearance "Silk to Solder Mask Opening" [IsPad] p1: minsilkscreentomaskgap=0.4 clearancetoexposedcopper=TRUE
SolderMaskExpansion [All] p1: expansion=1.97
Width W_BAT [InNet('V_BAT')] p1: maxlimit=205 minlimit=10 preferedwidth=60 minimp=50.000000 maximp=50.000000 favimp=50.000000
Width [All] p2: maxlimit=100 minlimit=3.94 preferedwidth=10 minimp=50.000000 maximp=50.000000 favimp=50.000000 checkconnectedcopper=TRUE
16 further rules are at their usual default settings.

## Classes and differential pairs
component class Header: J6 J7 J8 J9 J11 J12 J13 J15 J16 J17 J18 J19 J20 J21 J22 J27
component class ADAS_SF_Power_Buck_5V: C172 C173 C174 C175 C176 C177 C178 C179 C180 C181 C182 C183 C184 C185 C186 C187 C188 C189 C190 C191 C192 C193 C194 C195 D8 D9 D10 J21 L25 NT1 Q6 Q7 Q8 Q9 R103 R104 R105 R106 R107 R108 R109 R110 R111 R112 R113 R114 R115 R116 R117 R118 R119 R120 R121 R122 R123 R253 TP10 TP11 TP12 TP13 TP14 TP15 TP46 U10
component class ADAS_SF_Power_Buck_3V3_1V8_1V1: C155 C156 C157 C158 C159 C160 C161 C162 C163 C164 C165 C166 C167 C168 C169 C170 C171 C_PVIN1 C_PVIN2 C_PVIN3 C_VIN1 D5 D6 D7 J17 J18 J19 J20 L22 L23 L24 Q2 R85 R86 R87 R88 R89 R90 R91 R94 R95 R96 R97 R98 R99 R100 R101 R102 R200 R201 R214 R215 TP48 TP49 TP50 U9
component class ADAS_SF_Power_Boost_12V: C138 C139 C140 C141 C142 C143 C144 C145 C146 C147 C148 C149 C150 C151 C152 C153 C154 Cbst1 D3 D4 J16 L21 NT2 Q3 Q4 Q5 R73 R74 R75 R76 R77 R78 R79 R80 R81 R82 R83 R84 R187 Rsense1 TP47 U8
component class ADAS_SF_Power_Battery_Input: 9 C130 C131 C132 C133 C134 C135 C136 C137 D1 D2 J12 J13 J14 Q1 R172 R173 TP40 TP41 TP42 TP43 TP44 TP45 TP51 TP52 TP53 TP54 U7
component class ADAS_SF_Data_Radar_Mux: C296 C297 C298 C299 C300 C301 C302 C303 C304 C305 C306 C307 C308 C309 C310 C311 R229 R231 R232 R234 R236 R237 R239 R241 R242 R244 R246 R247 U23 U24 U25 U26
component class ADAS_SF_Data_MSP430: 0 C123 C124 C125 C126 C127 C128 C129 D11 D12 D13 D15 D16 D17 D18 D19 J6 J7 J8 J9 J10 J11 J15 R44 R45 R46 R49 R50 R51 R52 R53 R54 R55 R56 R57 R58 R59 R60 R61 R63 R64 R65 R66 R67 R68 R69 R70 R71 R72 R228 R230 R233 R235 R238 R240 R243 R248 R249 R250 S1 S2 S3 TP5 TP6 TP7 TP8 TP9 U3 U4 U5 U6
component class ADAS_SF_Data_Deserializer_Radar: C62 C63 C64 C65 C66 C67 C68 C69 C70 C71 C72 C73 C74 C75 C76 C77 C78 C79 C80 C81 C82 C83 C84 C85 C86 C87 C88 C89 C90 C91 C92 C93 C94 C95 C96 C97 C98 C99 C100 C101 C102 C103 C104 C105 C106 C107 C108 C109 C110 C111 C112 C113 C114 C115 C116 C117 C118 C119 C120 C121 C122 C313 L11 L12 L13 L14 L15 L16 L17 L18 L19 L20 L78 R31 R32 R33 R34 R35 R36 R37 R38 R39 R40 R41 R42 R43 R245 R251 R252 S5 TP3 TP4 TP55 U2 Y1
component class ADAS_SF_Data_Deserializer_Camera: C1 C2 C3 C4 C5 C6 C7 C8 C9 C10 C11 C12 C13 C14 C15 C16 C17 C18 C19 C20 C21 C22 C23 C24 C25 C26 C27 C28 C29 C30 C31 C32 C33 C34 C35 C36 C37 C38 C39 C40 C41 C42 C43 C44 C45 C46 C47 C48 C49 C50 C51 C52 C53 C54 C55 C56 C57 C58 C59 C60 C61 L1 L2 L3 L4 L5 L6 L7 L8 L9 L10 R21 R22 R23 R24 R25 R26 R27 R28 R29 R30 R186 S4 TP1 TP2 U1
component class ADAS_SF_Data_CSI2_Connector: C312 D14 J1 J40 R1 R2 R3 R4 R5 R6 R7 R8 R9 R10 R11 R12 R13 R14 R15 R16 R17 R18 R19 R20 R47 R48 R149 R150 R151 U27
component class ADAS_SF_Data_Connection_Radar_02: C266 C267 C268 C269 C270 C271 C272 C273 C274 C275 C276 C277 C278 C279 C281 C282 C283 C284 C285 C286 C287 C288 C289 C290 C291 C292 C293 C294 J32 J33 J34 J35 L56 L59 L60 L61 L63 L66 L67 L68 L70 L71 L72 L73 L74 L75 L76 L77 L85 L86 R127 R148 R202 R203 R204 R205 R206 R207 R208 R209 R210 R211 R212 R213 R216 R217 R218 R219 R220 R221 R222 R223 R224 R225 R226 R227 TP34 TP35 TP36 TP37 TP38 TP39 U19 U20 U21 U22
component class ADAS_SF_Data_Connection_Radar_01: C236 C237 C238 C239 C240 C241 C242 C243 C244 C245 C246 C247 C248 C249 C251 C252 C253 C254 C255 C256 C257 C258 C259 C260 C261 C262 C263 C264 J27 J28 J29 J30 J31 L42 L45 L46 L47 L49 L51 L52 L53 L54 L55 L57 L58 L62 L64 L65 L69 L83 L84 R125 R126 R168 R169 R170 R171 R174 R175 R176 R177 R178 R179 R180 R181 R182 R183 R184 R185 R188 R189 R190 R191 R192 R193 R194 R195 R196 R197 R198 R199 TP28 TP29 TP30 TP31 TP32 TP33 U15 U16 U17 U18
component class ADAS_SF_Data_Connection_Cam_02: C216 C217 C218 C219 C220 C221 C222 C223 C224 C225 C226 C227 C230 C231 C232 C233 C234 C235 J25 J26 L34 L35 L38 L39 L40 L41 L43 L44 L48 L50 L81 L82 R93 R124 R152 R153 R154 R155 R156 R157 R158 R159 R160 R161 R162 R163 R164 R165 R166 R167 TP22 TP23 TP24 TP25 TP26 TP27 U13 U14
component class ADAS_SF_Data_Connection_Cam_01: 0 C196 C197 C198 C199 C200 C201 C202 C203 C204 C205 C206 C207 C210 C211 C212 C213 C214 C215 J22 J23 J24 L26 L27 L28 L29 L30 L31 L32 L33 L36 L37 L79 L80 R62 R92 R128 R129 R130 R131 R132 R133 R134 R135 R136 R137 R138 R139 R140 R141 R142 R143 R144 R145 R146 R147 TP16 TP17 TP18 TP19 TP20 TP21 U11 U12
component class "Mounting Holes": H1 H2 H3 H4
component class Logo: Logo1
component class ADAS_SF_rev1_Hardware: FID1 FID2 FID3 FID4 FID5 FID6 H1 H2 H3 H4 H5 H6 H7 H8 Logo1 Logo2 Logo3 ZZ1 ZZ2 ZZ3 ZZ4
component class FiducialMark: FID1 FID2 FID3 FID4 FID5 FID6
component class AssemblyNote: ZZ1 ZZ2 ZZ3 ZZ4
differential pair RAD_D3: +RAD_D3_P -RAD_D3_N
differential pair RAD_D2: +RAD_D2_P -RAD_D2_N
differential pair RAD_D1: +RAD_D1_P -RAD_D1_N
differential pair RAD_D0: +RAD_D0_P -RAD_D0_N
differential pair RAD_CLK: +RAD_CLK_P -RAD_CLK_N
differential pair CAM_D3: +CAM_D3_P -CAM_D3_N
differential pair CAM_D2: +CAM_D2_P -CAM_D2_N
differential pair CAM_D1: +CAM_D1_P -CAM_D1_N
differential pair CAM_D0: +CAM_D0_P -CAM_D0_N
differential pair CAM_CLK: +CAM_CLK_P -CAM_CLK_N
differential pair RADAR_CSI0_D3: +RADAR_CSI0_D3_P -RADAR_CSI0_D3_N
differential pair RADAR_CSI0_D2: +RADAR_CSI0_D2_P -RADAR_CSI0_D2_N
differential pair RADAR_CSI0_D1: +RADAR_CSI0_D1_P -RADAR_CSI0_D1_N
differential pair RADAR_CSI0_D0: +RADAR_CSI0_D0_P -RADAR_CSI0_D0_N
differential pair RADAR_CSI0_CLK: +RADAR_CSI0_CLK_P -RADAR_CSI0_CLK_N
differential pair RADAR_3: +RADAR_3_P -RADAR_3_N
differential pair RADAR_3_HSD: +RADAR_3_HSD_P -RADAR_3_HSD_N
differential pair RADAR_3_COAX: +RADAR_3_COAX_P -RADAR_3_COAX_N
differential pair RADAR_2: +RADAR_2_P -RADAR_2_N
differential pair RADAR_2_HSD: +RADAR_2_HSD_P -RADAR_2_HSD_N
differential pair RADAR_2_COAX: +RADAR_2_COAX_P -RADAR_2_COAX_N
differential pair RADAR_1: +RADAR_1_P -RADAR_1_N
differential pair RADAR_1_HSD: +RADAR_1_HSD_P -RADAR_1_HSD_N
differential pair RADAR_1_COAX: +RADAR_1_COAX_P -RADAR_1_COAX_N
differential pair RADAR_0: +RADAR_0_P -RADAR_0_N
differential pair RADAR_0_HSD: +RADAR_0_HSD_P -RADAR_0_HSD_N
differential pair RADAR_0_COAX: +RADAR_0_COAX_P -RADAR_0_COAX_N
differential pair LPTX1: +LPTX1_P -LPTX1_N
differential pair LPTX0: +LPTX0_P -LPTX0_N
differential pair CAM_CSI0_D3: +CAM_CSI0_D3_P -CAM_CSI0_D3_N
differential pair CAM_CSI0_D2: +CAM_CSI0_D2_P -CAM_CSI0_D2_N
differential pair CAM_CSI0_D1: +CAM_CSI0_D1_P -CAM_CSI0_D1_N
differential pair CAM_CSI0_D0: +CAM_CSI0_D0_P -CAM_CSI0_D0_N
differential pair CAM_CSI0_CLK: +CAM_CSI0_CLK_P -CAM_CSI0_CLK_N
differential pair CAM_3: +CAM_3_P -CAM_3_N
differential pair CAM_2: +CAM_2_P -CAM_2_N
differential pair CAM_1: +CAM_1_P -CAM_1_N
differential pair CAM_0: +CAM_0_P -CAM_0_N

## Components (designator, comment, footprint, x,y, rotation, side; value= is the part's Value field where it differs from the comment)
C1 "CL21A106KAFN3NE" 0805_HV 3251.56,1686.87 r0 top value=10uF
C2 "CL21A106KAFN3NE" 0805_HV 3251.56,1686.87 r0 bottom value=10uF
C3 "C1005JB1V105K050BC" 0402#1 3097.56,1655.87 r0 bottom value=1uF
C4 "GCM155R71H104KE02D" 0402#1 3097.56,1705.87 r0 bottom value=0.1uF
C5 "GCM155R71H103KA55D" 0402#1 2682.56,1605.87 r90 bottom value=0.01uF
C6 "GCM155R71H103KA55D" 0402#1 3097.56,1705.87 r0 top value=0.01uF
C7 "CL21A106KAFN3NE" 0805_HV 2962.56,2020.87 r90 top value=10uF
C8 "CL21A106KAFN3NE" 0805_HV 2962.56,2020.87 r90 bottom value=10uF
C9 "C1005JB1V105K050BC" 0402#1 2992.56,1865.87 r90 bottom value=1uF
C10 "GCM155R71H104KE02D" 0402#1 2942.56,1865.87 r90 bottom value=0.1uF
C11 "GCM155R71H103KA55D" 0402#1 2622.56,1730.87 r270 top value=0.01uF
C12 "GCM155R71H103KA55D" 0402#1 2942.56,1865.87 r90 top value=0.01uF
C13 "CL21A106KAFN3NE" 0805_HV 2602.56,1235.87 r270 bottom value=10uF
C14 "CL21A106KAFN3NE" 0805_HV 2727.56,1200.87 r180 bottom value=10uF
C15 "C1005JB1V105K050BC" 0402#1 2722.56,1340.87 r180 bottom value=1uF
C16 "GCM155R71H104KE02D" 0402#1 2712.56,1445.87 r90 bottom value=0.1uF
C17 "GCM155R71H103KA55D" 0402#1 2762.56,1445.87 r90 bottom value=0.01uF
C18 "GCM155R71H103KA55D" 0402#1 2912.56,1445.87 r90 bottom value=0.01uF
C19 "GCM155R71H104KE02D" 0402#1 1965.75,1330.87 r270 top value=0.1uF
C20 "CL21A106KAFN3NE" 0805_HV 3705.6,1390.65 r90 top value=10uF
C21 "CL21A106KAFN3NE" 0805_HV 2632.56,2000.87 r180 top value=10uF
C22 "CL21A106KAFN3NE" 0805_HV 2632.56,2000.87 r180 bottom value=10uF
C23 "C1005JB1V105K050BC" 0402#1 2622.56,1875.87 r90 bottom value=1uF
C24 "GCM155R71H104KE02D" 0402#1 2687.56,1875.87 r90 bottom value=0.1uF
C25 "GCM155R71H103KA55D" 0402#1 2687.56,1875.87 r90 top value=0.01uF
C26 "GCM155R71H104KE02D" 0402#1 1495.18,776 r180 top value=0.1uF
C27 "CL21A106KAFN3NE" 0805_HV 3197.56,1300.87 r0 top value=10uF
C28 "CL21A106KAFN3NE" 0805_HV 3042.56,1265.87 r0 bottom value=10uF
C29 "C1005JB1V105K050BC" 0402#1 3017.56,1335.87 r0 bottom value=1uF
C30 "GCM155R71H104KE02D" 0402#1 3012.56,1445.87 r90 bottom value=0.1uF
C31 "GCM155R71H103KA55D" 0402#1 2662.56,1445.87 r90 bottom value=0.01uF
C32 "GCM155R71H103KA55D" 0402#1 2812.56,1445.87 r90 bottom value=0.01uF
C33 "GCM155R71H103KA55D" 0402#1 2862.56,1445.87 r90 bottom value=0.01uF
C34 "GCM155R71H103KA55D" 0402#1 2962.56,1445.87 r90 bottom value=0.01uF
C35 "CGA2B3X7R1H333K050BB" 0402#1 2815.56,1294.49 r270 top value=0.033uF
C36 "CL21A106KAFN3NE" 0805_HV 2407.56,1515.87 r180 top value=10uF
C37 "CL21A106KAFN3NE" 0805_HV 2407.56,1425.87 r180 bottom value=10uF
C38 "C1005JB1V105K050BC" 0402#1 2562.56,1395.87 r180 bottom value=1uF
C39 "GCM155R71H104KE02D" 0402#1 2562.56,1445.87 r180 bottom value=0.1uF
C40 "GCM155R71H103KA55D" 0402#1 2562.56,1445.87 r180 top value=0.01uF
C41 "CGA2B3X7R1H333K050BB" 0402#1 2865.56,1294.49 r270 top value=0.033uF
C42 "CL21A106KAFN3NE" 0805_HV 2407.56,1425.87 r180 top value=10uF
C43 "CL21A106KAFN3NE" 0805_HV 2407.56,1515.87 r180 bottom value=10uF
C44 "C1005JB1V105K050BC" 0402#1 2562.56,1545.87 r180 bottom value=1uF
C45 "GCM155R71H104KE02D" 0402#1 2562.56,1495.87 r180 bottom value=0.1uF
C46 "GCM155R71H103KA55D" 0402#1 2562.56,1495.87 r180 top value=0.01uF
C47 "CL21A106KAFN3NE" 0805_HV 3262.56,1416.87 r0 top value=10uF
C48 "CL21A106KAFN3NE" 0805_HV 3262.56,1416.87 r0 bottom value=10uF
C49 "C1005JB1V105K050BC" 0402#1 3107.56,1385.87 r0 bottom value=1uF
C50 "GCM155R71H104KE02D" 0402#1 3107.56,1435.87 r0 bottom value=0.1uF
C51 "GCM155R71H103KA55D" 0402#1 3107.56,1435.87 r0 top value=0.01uF
C52 "CL21A106KAFN3NE" 0805_HV 3262.56,1504.87 r0 top value=10uF
C53 "CL21A106KAFN3NE" 0805_HV 3262.56,1504.87 r0 bottom value=10uF
C54 "C1005JB1V105K050BC" 0402#1 3107.56,1535.87 r0 bottom value=1uF
C55 "GCM155R71H104KE02D" 0402#1 3107.56,1485.87 r0 bottom value=0.1uF
C56 "GCM155R71H103KA55D" 0402#1 3107.56,1485.87 r0 top value=0.01uF
C57 "CL21A106KAFN3NE" 0805_HV 3251.56,1774.87 r0 top value=10uF
C58 "CL21A106KAFN3NE" 0805_HV 3251.56,1774.87 r0 bottom value=10uF
C59 "C1005JB1V105K050BC" 0402#1 3097.56,1805.87 r0 bottom value=1uF
C60 "GCM155R71H104KE02D" 0402#1 3097.56,1755.87 r0 bottom value=0.1uF
C61 "GCM155R71H103KA55D" 0402#1 3097.56,1755.87 r0 top value=0.01uF
C62 "CL21A106KAFN3NE" 0805_HV 2438,3629 r270 top value=10uF
C63 "CL21A106KAFN3NE" 0805_HV 2438,3629 r270 bottom value=10uF
C64 "C1005JB1V105K050BC" 0402#1 2409,3785 r270 bottom value=1uF
C65 "GCM155R71H104KE02D" 0402#1 2458,3785 r270 bottom value=0.1uF
C66 "GCM155R71H103KA55D" 0402#1 2354,4195 r0 bottom value=0.01uF
C67 "GCM155R71H103KA55D" 0402#1 2458,3785 r270 top value=0.01uF
C68 "CL21A106KAFN3NE" 0805_HV 2745,3920 r270 top value=10uF
C69 "CL21A106KAFN3NE" 0805_HV 2745,3920 r270 bottom value=10uF
C70 "C1005JB1V105K050BC" 0402#1 2624,3923 r0 bottom value=1uF
C71 "GCM155R71H104KE02D" 0402#1 2624,3973 r0 bottom value=0.1uF
C72 "GCM155R71H103KA55D" 0402#1 2485,4283 r180 top value=0.01uF
C73 "GCM155R71H103KA55D" 0402#1 2624,3973 r0 top value=0.01uF
C74 "CL21A106KAFN3NE" 0805_HV 1980,4306 r90 bottom value=10uF
C75 "CL21A106KAFN3NE" 0805_HV 2069,4306 r90 bottom value=10uF
C76 "C1005JB1V105K050BC" 0402#1 2051,4137 r180 bottom value=1uF
C77 "GCM155R71H104KE02D" 0402#1 2192,4175.5 r0 bottom value=0.1uF
C78 "GCM155R71H103KA55D" 0402#1 2192,4125.5 r0 bottom value=0.01uF
C79 "GCM155R71H103KA55D" 0402#1 2192,3975.5 r0 bottom value=0.01uF
C80 "CL21A106KAFN3NE" 0805_HV 2779,4223 r0 top value=10uF
C81 "CL21A106KAFN3NE" 0805_HV 2779,4223 r0 bottom value=10uF
C82 "C1005JB1V105K050BC" 0402#1 2624,4253 r0 bottom value=1uF
C83 "GCM155R71H104KE02D" 0402#1 2624,4204 r0 bottom value=0.1uF
C84 "GCM155R71H103KA55D" 0402#1 2624,4204 r0 top value=0.01uF
C85 "GCM155R71H104KE02D" 0402#1 2140,4730 r0 top value=0.1uF
C86 "CL21A106KAFN3NE" 0805_HV 2089.54,2987.12 r0 top value=10uF
C87 "CL21A106KAFN3NE" 0805_HV 2012,3804 r180 top value=10uF
C88 "CL21A106KAFN3NE" 0805_HV 2012,3804 r180 bottom value=10uF
C89 "C1005JB1V105K050BC" 0402#1 2036.35,3889.7 r180 bottom value=1uF
C90 "GCM155R71H104KE02D" 0402#1 2192,3875.5 r0 bottom value=0.1uF
C91 "GCM155R71H103KA55D" 0402#1 2192,3925.5 r0 bottom value=0.01uF
C92 "GCM155R71H103KA55D" 0402#1 2192,4075.5 r0 bottom value=0.01uF
C93 "GCM155R71H103KA55D" 0402#1 2192,4025.5 r0 bottom value=0.01uF
C94 "GCM155R71H103KA55D" 0402#1 2192,4225.5 r0 bottom value=0.01uF
C95 "GCM155R71H104KE02D" 0402#1 2057.74,5349.2 r90 top value=0.1uF
C96 "CL21A106KAFN3NE" 0805_HV 2183,4473 r90 top value=10uF
C97 "CL21A106KAFN3NE" 0805_HV 2183,4473 r90 bottom value=10uF
C98 "C1005JB1V105K050BC" 0402#1 2152,4318 r90 bottom value=1uF
C99 "GCM155R71H104KE02D" 0402#1 2202.21,4318 r90 bottom value=0.1uF
C100 "GCM155R71H103KA55D" 0402#1 2202.21,4318 r90 top value=0.01uF
C101 "CGA2B3X7R1H333K050BB" 0402#1 2044,4073.19 r180 top value=0.033uF
C102 "CGA2B3X7R1H333K050BB" 0402#1 2044,4023.19 r180 top value=0.033uF
C103 "CL21A106KAFN3NE" 0805_HV 2272,4473 r90 top value=10uF
C104 "CL21A106KAFN3NE" 0805_HV 2272,4473 r90 bottom value=10uF
C105 "C1005JB1V105K050BC" 0402#1 2303,4318 r90 bottom value=1uF
C106 "GCM155R71H104KE02D" 0402#1 2252.21,4318 r90 bottom value=0.1uF
C107 "GCM155R71H103KA55D" 0402#1 2252.21,4318 r90 top value=0.01uF
C108 "CL21A106KAFN3NE" 0805_HV 2254,3629 r270 top value=10uF
C109 "CL21A106KAFN3NE" 0805_HV 2164,3629 r270 bottom value=10uF
C110 "C1005JB1V105K050BC" 0402#1 2134,3784 r270 bottom value=1uF
C111 "GCM155R71H104KE02D" 0402#1 2184,3784 r270 bottom value=0.1uF
C112 "GCM155R71H103KA55D" 0402#1 2184,3784 r270 top value=0.01uF
C113 "CL21A106KAFN3NE" 0805_HV 2164,3629 r270 top value=10uF
C114 "CL21A106KAFN3NE" 0805_HV 2254,3629 r270 bottom value=10uF
C115 "C1005JB1V105K050BC" 0402#1 2283,3784 r270 bottom value=1uF
C116 "GCM155R71H104KE02D" 0402#1 2234,3784 r270 bottom value=0.1uF
C117 "GCM155R71H103KA55D" 0402#1 2234,3784 r270 top value=0.01uF
C118 "CL21A106KAFN3NE" 0805_HV 2527,3629 r270 top value=10uF
C119 "CL21A106KAFN3NE" 0805_HV 2527,3629 r270 bottom value=10uF
C120 "C1005JB1V105K050BC" 0402#1 2557,3785 r270 bottom value=1uF
C121 "GCM155R71H104KE02D" 0402#1 2508,3785 r270 bottom value=0.1uF
C122 "GCM155R71H103KA55D" 0402#1 2508,3785 r270 top value=0.01uF
C123 "0603YC104JAT2A" 0603 5990.98,2801.56 r90 top value=0.1uF
C124 "GRM155R61A222KA01D" 0402#1 6465,3630 r270 top value=2200pF
C125 "GRM155R61A475M" 0402#1 5790,3635 r180 top value=4.7uF
C126 "GCM155R71H104KE02D" 0402#1 5745,3260 r180 top value=0.1uF
C127 "GRM155R61A222KA01D" 0402#1 6465,3875 r270 top value=2200pF
C128 "0603YC104JAT2A" 0603 6309.69,1945.63 r90 top value=0.1uF
C129 "0603YC104JAT2A" 0603 6316,2398.62 r90 top value=0.1uF
C130 "C3225X7S2A475K200AB" 1210_220 2767.72,6192.91 r270 bottom value=4.7uF
C131 "C3225X7S2A475K200AB" 1210_220 2909.45,6192.91 r270 bottom value=4.7uF
C132 "08055A101JAT2A" 0805_HV 1932.19,6346.48 r180 top value=100pF
C133 "GRM21BR71H105KA12L" 0805_HV 2656.02,5992.05 r270 top value=1uF
C134 "GRM21BC71H475KE11K" 0805_HV 2357.5,5992.05 r270 top value=4.7uF
C135 "GRM21BC71H475KE11K" 0805_HV 2456.02,5992.05 r270 top value=4.7uF
C136 "GRM21BC71H475KE11K" 0805_HV 2556.02,5992.05 r270 top value=4.7uF
C137 "C2012X5R1H225K125AB" 0805_HV 1813.69,6099.04 r90 top value=2.2uF
C138 "EEEFPE561UAP" Panasonic_G 4905,4850 r180 top value=560uF
C139 "GRM21BC81E335KA73L" 0805_HV 5030,4410 r180 top value=3.3uF
C140 "GRM21BC81E335KA73L" 0805_HV 5030,4500 r180 top value=3.3uF
C141 "GRM21BC81E335KA73L" 0805_HV 5030.59,4590 r180 top value=3.3uF
C142 "16SVPE470M" CAPSMT_62_JC0 3755,4365 r180 top value=470uF
C143 "16SVPE470M" CAPSMT_62_JC0 3755,4800 r180 top value=470uF
C144 "CL21A106KAFN3NE" 0805_HV 4170.59,4586.48 r0 top value=10uF
C145 "CL21A106KAFN3NE" 0805_HV 4170.59,4676.48 r0 top value=10uF
C146 "CL21A106KAFN3NE" 0805_HV 4170.59,4766.48 r0 top value=10uF
C147 "CL21A106KAFN3NE" 0805_HV 4170.59,4856.48 r0 top value=10uF
C148 "GRM188R61E475KE11D" 0603 3363.84,4495.86 r270 bottom value=4.7uF
C149 "GRM1555C1H101JA01D" 0402#1 3523.84,4550.86 r180 bottom value=100pF
C150 "GCM155R71H104KE02D" 0402#1 3193.84,4495.86 r270 bottom value=0.1uF
C151 "GRM155R61A154KE19D" 0402#1 3218.84,5066.69 r90 bottom value=0.15uF
C152 "GRM21BC71H475KE11K" 0805_HV 3293.84,5095.31 r270 bottom value=4.7uF
C153 "GRM155R71H152KA01D" 0402#1 3228.84,4804.66 r90 bottom value=1500pF
C154 "CGA2B3X7R1H153K050BB" 0402#1 3148.84,4779.66 r180 bottom value=0.015uF
C155 "GRM155R60J473KA01D" 0402#1 6195,5120 r90 top value=0.047uF
C156 "GRM188R61A226ME15D" 0603 6182,5560 r180 top value=22uF
C157 "GRM155R71H152KA01D" 0402#1 6360,5111.38 r270 top value=1500pF
C158 "EEE-FC0J470R" SM_RADIAL_C 5885,5475 r180 top value=47uF
C159 "GRM1555C1H180JA01D" 0402#1 6445,5136.38 r0 top value=18pF
C160 "GRM155R60J473KA01D" 0402#1 5920,4785 r270 top value=0.047uF
C161 "GRM188R61A226ME15D" 0603 5942,4347 r0 top value=22uF
C162 "GRM155R61A222KA01D" 0402#1 5781.22,4860 r0 top value=2200pF
C163 "GRM1555C1H510JA01D" 0402#1 5781.02,4912.04 r0 top value=51pF
C164 "GRM155R60J473KA01D" 0402#1 6195,4785 r270 top value=0.047uF
C165 "GRM188R61A226ME15D" 0603 6175,4347 r180 top value=22uF
C166 "GRM155R71H272KA01D" 0402#1 6360,4891.65 r90 top value=2700pF
C167 "C1005JB1V105K050BC" 0402#1 5840,5105 r180 top value=1uF
C168 "GRM155R71C103KA01D" 0402#1 6275,5095 r0 top
C169 "GRM155R71C103KA01D" 0402#1 5780,4805 r180 top
C170 "GRM155R71C103KA01D" 0402#1 6280,4810 r0 top
C171 "GRM1555C1H910JA01D" 0402#1 6280,4866.65 r180 top value=91pF
C172 "CGA5L3X5R1H106K160AB" 1206_190 3717.72,6303.84 r270 top value=10uF
C173 "CGA5L3X5R1H106K160AB" 1206_190 3807.4,6303.84 r270 top value=10uF
C174 "CGA5L3X5R1H106K160AB" 1206_190 3897.72,6303.84 r270 top value=10uF
C175 "2.2µF" 1206 3997.72,6296.93 r270 top
C176 "GCM155R71H104KE02D" 0402#1 3439.57,5601.38 r270 top value=0.1uF
C177 "GRM1555C1E470JA01D" 0402#1 3590.95,5601.38 r90 top value=47pF
C178 "GRM21AR72A334KAC5L" 0805_HV 3736.38,5991.38 r0 top value=0.33uF
C179 "GRM21BR72A474KA73L" 0805_HV 3501.38,6003.05 r270 bottom value=0.47uF
C180 "C0603C225M8PACTU" 0603_HV 3726.38,5845 r0 top value=2.2uF
C181 "C0603C225M8PACTU" 0603_HV 3726.38,5785 r180 top value=2.2uF
C182 "08051A471JAT2A" 0805_HV 4315,5635 r90 bottom value=470pF
C183 "GRM31CR61A476KE15L" 1206_180 5360,6325 r90 top value=47uF
C184 "APXA6R3ARA221MH70G" CAPSMT_62_H70 5980,6335 r90 top value=220uF
C185 "APXA6R3ARA221MH70G" CAPSMT_62_H70 6278,6035 r0 top value=220uF
C186 "GRM188R72A104KA35D" 0603L 5235,6295 r270 top value=0.1uF
C187 "GRM31CR61A476KE15L" 1206_180 5455,6325 r90 top value=47uF
C188 "GRM31CR61A476KE15L" 1206_180 5550,6325 r90 top value=47uF
C189 "GRM31CR61A476KE15L" 1206_180 5645,6325 r90 top value=47uF
C190 "GRM188R72A104KA35D" 0603L 5285,6295 r270 top value=0.1uF
C191 "06031A330JAT2A" 0603L 3373.03,5956.38 r180 top value=33pF
C192 "GRM155R61A224KE19D" 0402#1 3254.57,5726.38 r180 top value=0.22uF
C193 "GCM155R71H103KA55D" 0402#1 3254.57,5676.38 r180 top value=0.01uF
C194 "GRM1555C1E471JA01D" 0402#1 3284.57,5808.03 r270 top value=470pF
C195 "GRM155R71C223KA01D" 0402#1 3204.57,5838.03 r0 top value=0.022uF
C196 "GCM155R71H104KE02D" 0402#1 757.27,199.13 r180 bottom value=0.1uF
C197 "TMK212BBJ106KG-T" 0805_HV 732.27,125.13 r180 bottom value=10uF
C198 "GCM155R71H104KE02D" 0402#1 754.65,393.87 r180 bottom value=0.1uF
C199 "TMK212BBJ106KG-T" 0805_HV 732.93,470.96 r180 bottom value=10uF
C200 "GCM155R71H104KE02D" 0402#1 1746.93,196.41 r180 bottom value=0.1uF
C201 "TMK212BBJ106KG-T" 0805_HV 1726.93,121.41 r180 bottom value=10uF
C202 "GCM155R71H104KE02D" 0402#1 1741.93,391.41 r180 bottom value=0.1uF
C203 "TMK212BBJ106KG-T" 0805_HV 1716.93,481.41 r180 bottom value=10uF
C204 "GCM155R71H104KE02D" 0402#1 2460,1239 r180 top value=0.1uF
C205 "GCM155R71H104KE02D" 0402#1 2606,1107 r180 top value=0.1uF
C206 "CGA2B3X7R1H473K050BB" 0402#1 2460,1190 r0 top value=0.047uF
C207 "CGA2B3X7R1H473K050BB" 0402#1 2606,1057 r0 top value=0.047uF
C210 "GRM188R72A104KA35D" 0603L 1017.56,1010.87 r180 top value=0.1uF
C211 "GRM188R72A104KA35D" 0603L 2017.56,1005.87 r180 top value=0.1uF
C212 "EEE-FC1C101P" SM_RADIAL_E 1017.56,610.87 r180 top value=100uF
C213 "EEE-FC1C101P" SM_RADIAL_E 2017.56,610.87 r180 top value=100uF
C214 "GCM155R71H102KA37D" 0402#1 757.56,960.87 r90 top value=1000pF
C215 "GCM155R71H102KA37D" 0402#1 1752.56,955.87 r90 top value=1000pF
C216 "GCM155R71H104KE02D" 0402#1 2756.93,196.92 r180 bottom value=0.1uF
C217 "TMK212BBJ106KG-T" 0805_HV 2731.93,121.92 r180 bottom value=10uF
C218 "GCM155R71H104KE02D" 0402#1 2756.93,391.92 r180 bottom value=0.1uF
C219 "TMK212BBJ106KG-T" 0805_HV 2736.93,466.92 r180 bottom value=10uF
C220 "GCM155R71H104KE02D" 0402#1 3761.93,201.92 r180 bottom value=0.1uF
C221 "TMK212BBJ106KG-T" 0805_HV 3736.93,126.92 r180 bottom value=10uF
C222 "GCM155R71H104KE02D" 0402#1 3756.93,391.92 r180 bottom value=0.1uF
C223 "TMK212BBJ106KG-T" 0805_HV 3731.93,471.92 r180 bottom value=10uF
C224 "GCM155R71H104KE02D" 0402#1 3334.56,1012.87 r270 top value=0.1uF
C225 "GCM155R71H104KE02D" 0402#1 3384,1179 r0 top value=0.1uF
C226 "CGA2B3X7R1H473K050BB" 0402#1 3386.56,1012.87 r90 top value=0.047uF
C227 "CGA2B3X7R1H473K050BB" 0402#1 3385,1230 r180 top value=0.047uF
C230 "GRM188R72A104KA35D" 0603L 2997.56,1020.87 r180 top value=0.1uF
C231 "GRM188R72A104KA35D" 0603L 4012.56,1005.87 r180 top value=0.1uF
C232 "EEE-FC1C101P" SM_RADIAL_E 3017.56,610.87 r180 top value=100uF
C233 "EEE-FC1C101P" SM_RADIAL_E 4017.05,606 r180 top value=100uF
C234 "GCM155R71H102KA37D" 0402#1 2742.56,970.87 r90 top value=1000pF
C235 "GCM155R71H102KA37D" 0402#1 3752.56,955.87 r90 top value=1000pF
C236 "GCM155R71H104KE02D" 0402#1 1209,6249.5 r0 top value=0.1uF
C237 "TMK212BBJ106KG-T" 0805_HV 1212,6322.5 r0 top value=10uF
C238 "GCM155R71H104KE02D" 0402#1 1209,6150.5 r0 top value=0.1uF
C239 "TMK212BBJ106KG-T" 0805_HV 1213,6069.5 r0 top value=10uF
C240 "GRM188R72A104KA35D" 0603L 1655,5592 r90 top value=0.1uF
C241 "GCM155R71H104KE02D" 0402#1 591.81,5582 r90 bottom value=0.1uF
C242 "EEE-FC1C101P" SM_RADIAL_E 1240,5507 r270 top value=100uF
C243 "CL21A106KAFN3NE" 0805_HV 983,5452.38 r0 top value=10uF
C244 "GCM155R71H104KE02D" 0402#1 536.81,5582 r90 bottom value=0.1uF
C245 "GCM155R71H104KE02D" 0402#1 526.28,5964.02 r90 bottom value=0.1uF
C246 "GCM155R71H102KA37D" 0402#1 1600,5807 r0 top value=1000pF
C247 "GRM188R72A104KA35D" 0603 703,5372.38 r90 top value=0.1uF
C248 "GRM188R72A104KA35D" 0603 703,5532.38 r270 top value=0.1uF
C249 "CGA2B3X7R1H473K050BB" 0402#1 500.28,5888.02 r0 bottom value=0.047uF
C251 "GCM155R71H104KE02D" 0402#1 1209,5003.5 r0 top value=0.1uF
C252 "TMK212BBJ106KG-T" 0805_HV 1211,5080.5 r0 top value=10uF
C253 "GCM155R71H104KE02D" 0402#1 1209,4906.5 r0 top value=0.1uF
C254 "TMK212BBJ106KG-T" 0805_HV 1213,4827.5 r0 top value=10uF
C255 "GRM188R72A104KA35D" 0603L 1655,4350 r90 top value=0.1uF
C256 "GCM155R71H104KE02D" 0402#1 589,4341 r90 bottom value=0.1uF
C257 "EEE-FC1C101P" SM_RADIAL_E 1240,4265 r270 top value=100uF
C258 "CL21A106KAFN3NE" 0805_HV 977.91,4243.62 r0 top value=10uF
C259 "GCM155R71H104KE02D" 0402#1 530,4340 r90 bottom value=0.1uF
C260 "GCM155R71H104KE02D" 0402#1 529,4721.97 r90 bottom value=0.1uF
C261 "GCM155R71H102KA37D" 0402#1 1600,4570 r0 top value=1000pF
C262 "GRM188R72A104KA35D" 0603 702.91,4163.58 r90 top value=0.1uF
C263 "GRM188R72A104KA35D" 0603 702.91,4323.58 r270 top value=0.1uF
C264 "CGA2B3X7R1H473K050BB" 0402#1 501,4645.97 r0 bottom value=0.047uF
C266 "GCM155R71H104KE02D" 0402#1 1207.38,3743.62 r0 top value=0.1uF
C267 "TMK212BBJ106KG-T" 0805_HV 1210.38,3826.62 r0 top value=10uF
C268 "GCM155R71H104KE02D" 0402#1 1209.38,3655.62 r0 top value=0.1uF
C269 "TMK212BBJ106KG-T" 0805_HV 1213.38,3575.62 r0 top value=10uF
C270 "GRM188R72A104KA35D" 0603L 1655,3108 r90 top value=0.1uF
C271 "GCM155R71H104KE02D" 0402#1 592,3095 r90 bottom value=0.1uF
C272 "EEE-FC1C101P" SM_RADIAL_E 1240,3023 r270 top value=100uF
C273 "CL21A106KAFN3NE" 0805_HV 978,3002 r0 top value=10uF
C274 "GCM155R71H104KE02D" 0402#1 530,3095 r90 bottom value=0.1uF
C275 "GCM155R71H104KE02D" 0402#1 524.5,3480 r90 bottom value=0.1uF
C276 "GCM155R71H102KA37D" 0402#1 1600,3328 r0 top value=1000pF
C277 "GRM188R72A104KA35D" 0603 703,2922 r90 top value=0.1uF
C278 "GRM188R72A104KA35D" 0603 703,3087 r270 top value=0.1uF
C279 "CGA2B3X7R1H473K050BB" 0402#1 495.5,3404 r0 bottom value=0.047uF
C281 "GCM155R71H104KE02D" 0402#1 1213,2508 r0 top value=0.1uF
C282 "TMK212BBJ106KG-T" 0805_HV 1213,2585 r0 top value=10uF
C283 "GCM155R71H104KE02D" 0402#1 1215,2411 r0 top value=0.1uF
C284 "TMK212BBJ106KG-T" 0805_HV 1213,2333 r0 top value=10uF
C285 "GRM188R72A104KA35D" 0603L 1655,1866 r90 top value=0.1uF
C286 "GCM155R71H104KE02D" 0402#1 590,1855 r90 bottom value=0.1uF
C287 "EEE-FC1C101P" SM_RADIAL_E 1240,1781 r270 top value=100uF
C288 "CL21A106KAFN3NE" 0805_HV 978,1760 r0 top value=10uF
C289 "GCM155R71H104KE02D" 0402#1 530,1855 r90 bottom value=0.1uF
C290 "GCM155R71H104KE02D" 0402#1 528,2238 r90 bottom value=0.1uF
C291 "GCM155R71H102KA37D" 0402#1 1595,2086 r0 top value=1000pF
C292 "GRM188R72A104KA35D" 0603 703,1680 r90 top value=0.1uF
C293 "GRM188R72A104KA35D" 0603 703,1845 r270 top value=0.1uF
C294 "CGA2B3X7R1H473K050BB" 0402#1 500,2162 r0 bottom value=0.047uF
C296 "CL21A106KAFN3NE" 0805_HV 983,5813 r270 bottom value=10uF
C297 "C1005JB1V105K050BC" 0402#1 893,5838 r270 bottom value=1uF
C298 "GCM155R71H104KE02D" 0402#1 838,5838 r270 bottom value=0.1uF
C299 "GCM155R71H103KA55D" 0402#1 786,5838 r270 bottom value=0.01uF
C300 "CL21A106KAFN3NE" 0805_HV 980,4566.38 r270 bottom value=10uF
C301 "C1005JB1V105K050BC" 0402#1 905,4591.38 r270 bottom value=1uF
C302 "GCM155R71H104KE02D" 0402#1 850,4591.38 r270 bottom value=0.1uF
C303 "GCM155R71H103KA55D" 0402#1 795,4591.38 r270 bottom value=0.01uF
C304 "CL21A106KAFN3NE" 0805_HV 979,3332.31 r270 bottom value=10uF
C305 "C1005JB1V105K050BC" 0402#1 904,3357.31 r270 bottom value=1uF
C306 "GCM155R71H104KE02D" 0402#1 849,3357.31 r270 bottom value=0.1uF
C307 "GCM155R71H103KA55D" 0402#1 794,3357.31 r270 bottom value=0.01uF
C308 "CL21A106KAFN3NE" 0805_HV 974,2085.31 r270 bottom value=10uF
C309 "C1005JB1V105K050BC" 0402#1 899,2110.31 r270 bottom value=1uF
C310 "GCM155R71H104KE02D" 0402#1 844,2110.31 r270 bottom value=0.1uF
C311 "GCM155R71H103KA55D" 0402#1 789,2110.31 r270 bottom value=0.01uF
C312 "GCM155R71H104KE02D" 0402#1 6035,2330 r270 top value=0.1uF
C313 "GCM155R71H104KE02D" 0402#1 2280.76,2108.76 r90 bottom value=0.1uF
C_PVIN1 "GRT188C81A106ME13D" 0603 6095,5360 r270 top value=10uF
C_PVIN2 "GRT188C81A106ME13D" 0603 6015,4540 r90 top value=10uF
C_PVIN3 "GRT188C81A106ME13D" 0603 6095,4540 r90 top value=10uF
C_VIN1 "C1005JB1V105K050BC" 0402#1 6015,5130 r90 top value=1uF
Cbst1 "GRM188R72A104KA35D" 0603 3453.84,5060.86 r0 bottom value=0.1uF
D1 "SMBJ28A-13-F" SMB 2401.02,6267.05 r270 top value=28V
D2 "SMBJ14A-13-F" SMB 2621.02,6192.05 r180 top value=14V
D3 "FSV20100V" TO-277A 4840,4255 r180 bottom value=100V
D4 "B230-13-F" SMB 3388.84,5270.86 r180 bottom value=30V
D5 "SML-P12MTT86" SML-P1_YELLOW-GREEN 6180,5674.76 r0 top value=Yellow/green
D6 "SML-P12YTT86" LED_SMLP12_Yellow 5638.35,4220 r0 top value=Yellow
D7 "SML-P12PTT86" SML-P1_GREEN 6571.57,4096.96 r0 top value=Green
D8 "B170-13-F" SMA 4105,5680 r180 bottom value=70V
D9 "PMEG6010CEJ,115" SOD-323F 3736.38,5911.38 r0 top value=60V
D10 "SML-P12DTT86" LED_SMLP12_ORANGE 5650,5965 r0 top value=Orange
D11 "SML-P12YTT86" LED_SMLP12_Yellow 6369.5,3945 r90 top value=Yellow
D12 "SML-P12DTT86" LED_SMLP12_ORANGE 6319.5,3945 r90 top value=Orange
D13 "SML-P12PTT86" SML-P1_GREEN 6274.5,3945 r270 top value=Green
D14 "VS-30BQ100HM3/9AT" SMC 6148.62,157.48 r0 bottom value=100V
D15 "SML-P12PTT86" SML-P1_GREEN 5885,3941.91 r270 top value=Green
D16 "SML-P12YTT86" LED_SMLP12_Yellow 5846,3941.62 r90 top value=Yellow
D17 "SML-P12DTT86" LED_SMLP12_ORANGE 5806,3941.62 r90 top value=Orange
D18 "SML-P12PTT86" SML-P1_GREEN 5939,3940.62 r270 top value=Green
D19 "SML-P12PTT86" SML-P1_GREEN 5994,3940.62 r270 top value=Green
FID1 "Fiducial" Fiducial10-20 172.7,473 r0 top
FID2 "Fiducial" Fiducial10-20 6520.32,6235 r0 top
FID3 "Fiducial" Fiducial10-20 458,6522 r0 top
FID4 "Fiducial" Fiducial10-20 6520.32,6235 r180 bottom
FID5 "Fiducial" Fiducial10-20 172.7,473 r180 bottom
FID6 "Fiducial" Fiducial10-20 458,6522 r180 bottom
H1 "NY PMS 440 0025 PH" "NY PMS 440 0025 PH"#1 6475,1363 r90 top
H2 "NY PMS 440 0025 PH" "NY PMS 440 0025 PH"#2 6475.01,6474.7 r90 top
H3 "NY PMS 440 0025 PH" "NY PMS 440 0025 PH"#3 350.01,1325.23 r90 top
H4 "NY PMS 440 0025 PH" "NY PMS 440 0025 PH"#4 182.01,6475.23 r90 top
H5 "1902C" Keystone_1902C 6474.99,1362.24 r90 bottom
H6 "1902C" Keystone_1902C 6475,6474.47 r90 bottom
H7 "1902C" Keystone_1902C 350,1325 r90 bottom
H8 "1902C" Keystone_1902C 182.01,6475.23 r90 bottom
J1 "QTH-020-01-L-D-DP-A" SAMTEC_QTH-020-01-L-D-DP-A 6093.88,871 r180 bottom
J6 "TSW-104-07-G-S" TSW-104-07-G-S 5425,3255 r270 top
J7 "TSW-104-07-G-S" TSW-104-07-G-S 5765.98,2802.86 r270 top
J8 "TSW-104-07-G-S" TSW-104-07-G-S 6445.98,2812.86 r270 top
J9 "TSW-104-07-G-S" TSW-104-07-G-S 6160.98,2972.86 r0 top
J10 "LPPB061NGCN-RC" SULLINS_LPPB061NGCN-RC 6724.02,3407.81 r90 top
J11 "TSW-104-07-G-S" TSW-104-07-G-S 6350,2145 r180 top
J12 "TSW-102-07-G-S" TSW-102-07-G-S 2610,6355 r180 top
J13 "TSW-102-07-G-S" TSW-102-07-G-S 2895.12,5982.32 r270 top
J14 "1757242" PHOENIX_1757242 3070,6375 r0 top
J15 "TSW-105-07-G-D" TSW-105-07-G-D 6344.78,1613.26 r180 top
J16 "TSW-102-07-G-S" TSW-102-07-G-S 3630,4000 r270 top
J17 "TSW-102-07-G-S" TSW-102-07-G-S 5920,5655 r0 top
J18 "TSW-102-07-G-S" TSW-102-07-G-S 6330,5690 r90 top
J19 "TSW-102-07-G-S" TSW-102-07-G-S 5775,4220 r270 top
J20 "TSW-102-07-G-S" TSW-102-07-G-S 6355,4220 r270 top
J21 "TSW-102-07-G-S" TSW-102-07-G-S 5485,5980 r270 top
J22 "TSW-103-07-G-S" TSW-103-07-G-S 4408.74,3407.39 r180 top
J23 "59S20X-400L5-Y" Rosenberger_59S20X-400L5 1337.56,75.87 r270 top
J24 "59S20X-400L5-Y" Rosenberger_59S20X-400L5 2337.56,75.87 r270 top
J25 "59S20X-400L5-Y" Rosenberger_59S20X-400L5 3337.56,75.87 r270 top
J26 "59S20X-400L5-Y" Rosenberger_59S20X-400L5 4337.56,75.87 r270 top
J27 "TSW-103-07-G-S" TSW-103-07-G-S 4085,3375 r90 top
J28 "59S20X-400L5-Y" Rosenberger_59S20X-400L5 75,6107 r180 top
J29 "D4S20L-40MA5-Z" Rosenberger_D4S20L-40MA5 0,5487 r270 top
J30 "59S20X-400L5-Y" Rosenberger_59S20X-400L5 75,4866 r180 top
J31 "D4S20L-40MA5-Z" Rosenberger_D4S20L-40MA5 0,4245 r270 top
J32 "59S20X-400L5-Y" Rosenberger_59S20X-400L5 75,3624 r180 top
J33 "D4S20L-40MA5-Z" Rosenberger_D4S20L-40MA5 0,3003 r270 top
J34 "59S20X-400L5-Y" Rosenberger_59S20X-400L5 75,2382 r180 top
J35 "D4S20L-40MA5-Z" Rosenberger_D4S20L-40MA5 0,1761 r270 top
J40 "1757242" PHOENIX_1757242 6044.88,345 r180 top
L1 "BLM18SG121TN1D" 0603 3109.56,1648.87 r180 top value="120 ohm"
L2 "BLM18SG121TN1D" 0603 2999.56,1877.87 r270 top value="120 ohm"
L3 "BLM18SG121TN1D" 0603 2722.56,1280.87 r0 bottom value="120 ohm"
L4 "BLM18SG121TN1D" 0603 2617.56,1885.87 r270 top value="120 ohm"
L5 "BLM18SG121TN1D" 0603 3052.56,1315.87 r180 top value="120 ohm"
L6 "BLM18SG121TN1D" 0603 2550.56,1388.87 r0 top value="120 ohm"
L7 "BLM18SG121TN1D" 0603 2550.56,1552.87 r0 top value="120 ohm"
L8 "BLM18SG121TN1D" 0603 3119.56,1378.87 r180 top value="120 ohm"
L9 "BLM18SG121TN1D" 0603 3119.56,1542.87 r180 top value="120 ohm"
L10 "BLM18SG121TN1D" 0603 3109.56,1812.87 r180 top value="120 ohm"
L11 "BLM18SG121TN1D" 0603 2402,3773 r90 top value="120 ohm"
L12 "BLM18SG121TN1D" 0603 2636,3916 r180 top value="120 ohm"
L13 "BLM18SG121TN1D" 0603 2048,4196 r0 bottom value="120 ohm"
L14 "BLM18SG121TN1D" 0603 2636,4260 r180 top value="120 ohm"
L15 "BLM18SG121TN1D" 0603 2024.35,3882.7 r0 top value="120 ohm"
L16 "BLM18SG121TN1D" 0603 2145,4330 r270 top value="120 ohm"
L17 "BLM18SG121TN1D" 0603 2310,4330 r270 top value="120 ohm"
L18 "BLM18SG121TN1D" 0603 2127,3772 r90 top value="120 ohm"
L19 "BLM18SG121TN1D" 0603 2290,3772 r90 top value="120 ohm"
L20 "BLM18SG121TN1D" 0603 2564,3773 r90 top value="120 ohm"
L21 "XAL1010-682MEB" XAL1010 4495,4040 r180 top value=6.8uH
L22 "SDR0805-4R7ML" SDR0805 6340,5350 r90 top value=4.7uH
L23 "SDR0805-4R7ML" SDR0805 5775,4555 r270 top value=4.7uH
L24 "SDR0805-4R7ML" SDR0805 6340,4555 r270 top value=4.7uH
L25 "XAL1010-222MEB" XAL1010 4560,5690 r0 top value=2.2uH
L26 "MPZ1608S102ATA00" 0603 777.34,293.18 r90 bottom value="1000 ohm"
L27 "MPZ1608S102ATA00" 0603 1766.93,291.41 r90 bottom value="1000 ohm"
L28 "LQH3NPZ100MJRL" LQH3NPZ_JR 925,470 r180 bottom value=10uH
L29 "LQH3NPZ100MJRL" LQH3NPZ_JR 1916.93,471.41 r180 bottom value=10uH
L30 "BLM18HE152SN1D" 0603 1069.95,508.45 r180 bottom value="1500 ohm"
L31 "BLM18HE152SN1D" 0603 2056.93,506.41 r180 bottom value="1500 ohm"
L32 "BLM18HE152SN1D" 0603 1203.94,508.45 r180 bottom value="1500 ohm"
L33 "BLM18HE152SN1D" 0603 2196.93,506.41 r180 bottom value="1500 ohm"
L34 "MPZ1608S102ATA00" 0603 2776.93,291.92 r90 bottom value="1000 ohm"
L35 "MPZ1608S102ATA00" 0603 3781.93,293.42 r90 bottom value="1000 ohm"
L36 "BLM18HE152SN1D" 0603 1290,441 r180 bottom value="1500 ohm"
L37 "BLM18HE152SN1D" 0603 2291,442 r180 bottom value="1500 ohm"
L38 "LQH3NPZ100MJRL" LQH3NPZ_JR 2926.93,466.92 r180 bottom value=10uH
L39 "LQH3NPZ100MJRL" LQH3NPZ_JR 3926.93,476.92 r180 bottom value=10uH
